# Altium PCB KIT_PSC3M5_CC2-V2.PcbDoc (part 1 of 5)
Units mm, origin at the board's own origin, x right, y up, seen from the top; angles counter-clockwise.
Board outline 131.5 x 87 mm, 6 copper layers (Top Layer, Int1 (GND), Int2 (Sign), Int3 (Sign), Int4 (PWR), Bottom Layer), stack 1.551 mm thick; 371 components, 253 nets, 1359 pads, 837 vias.
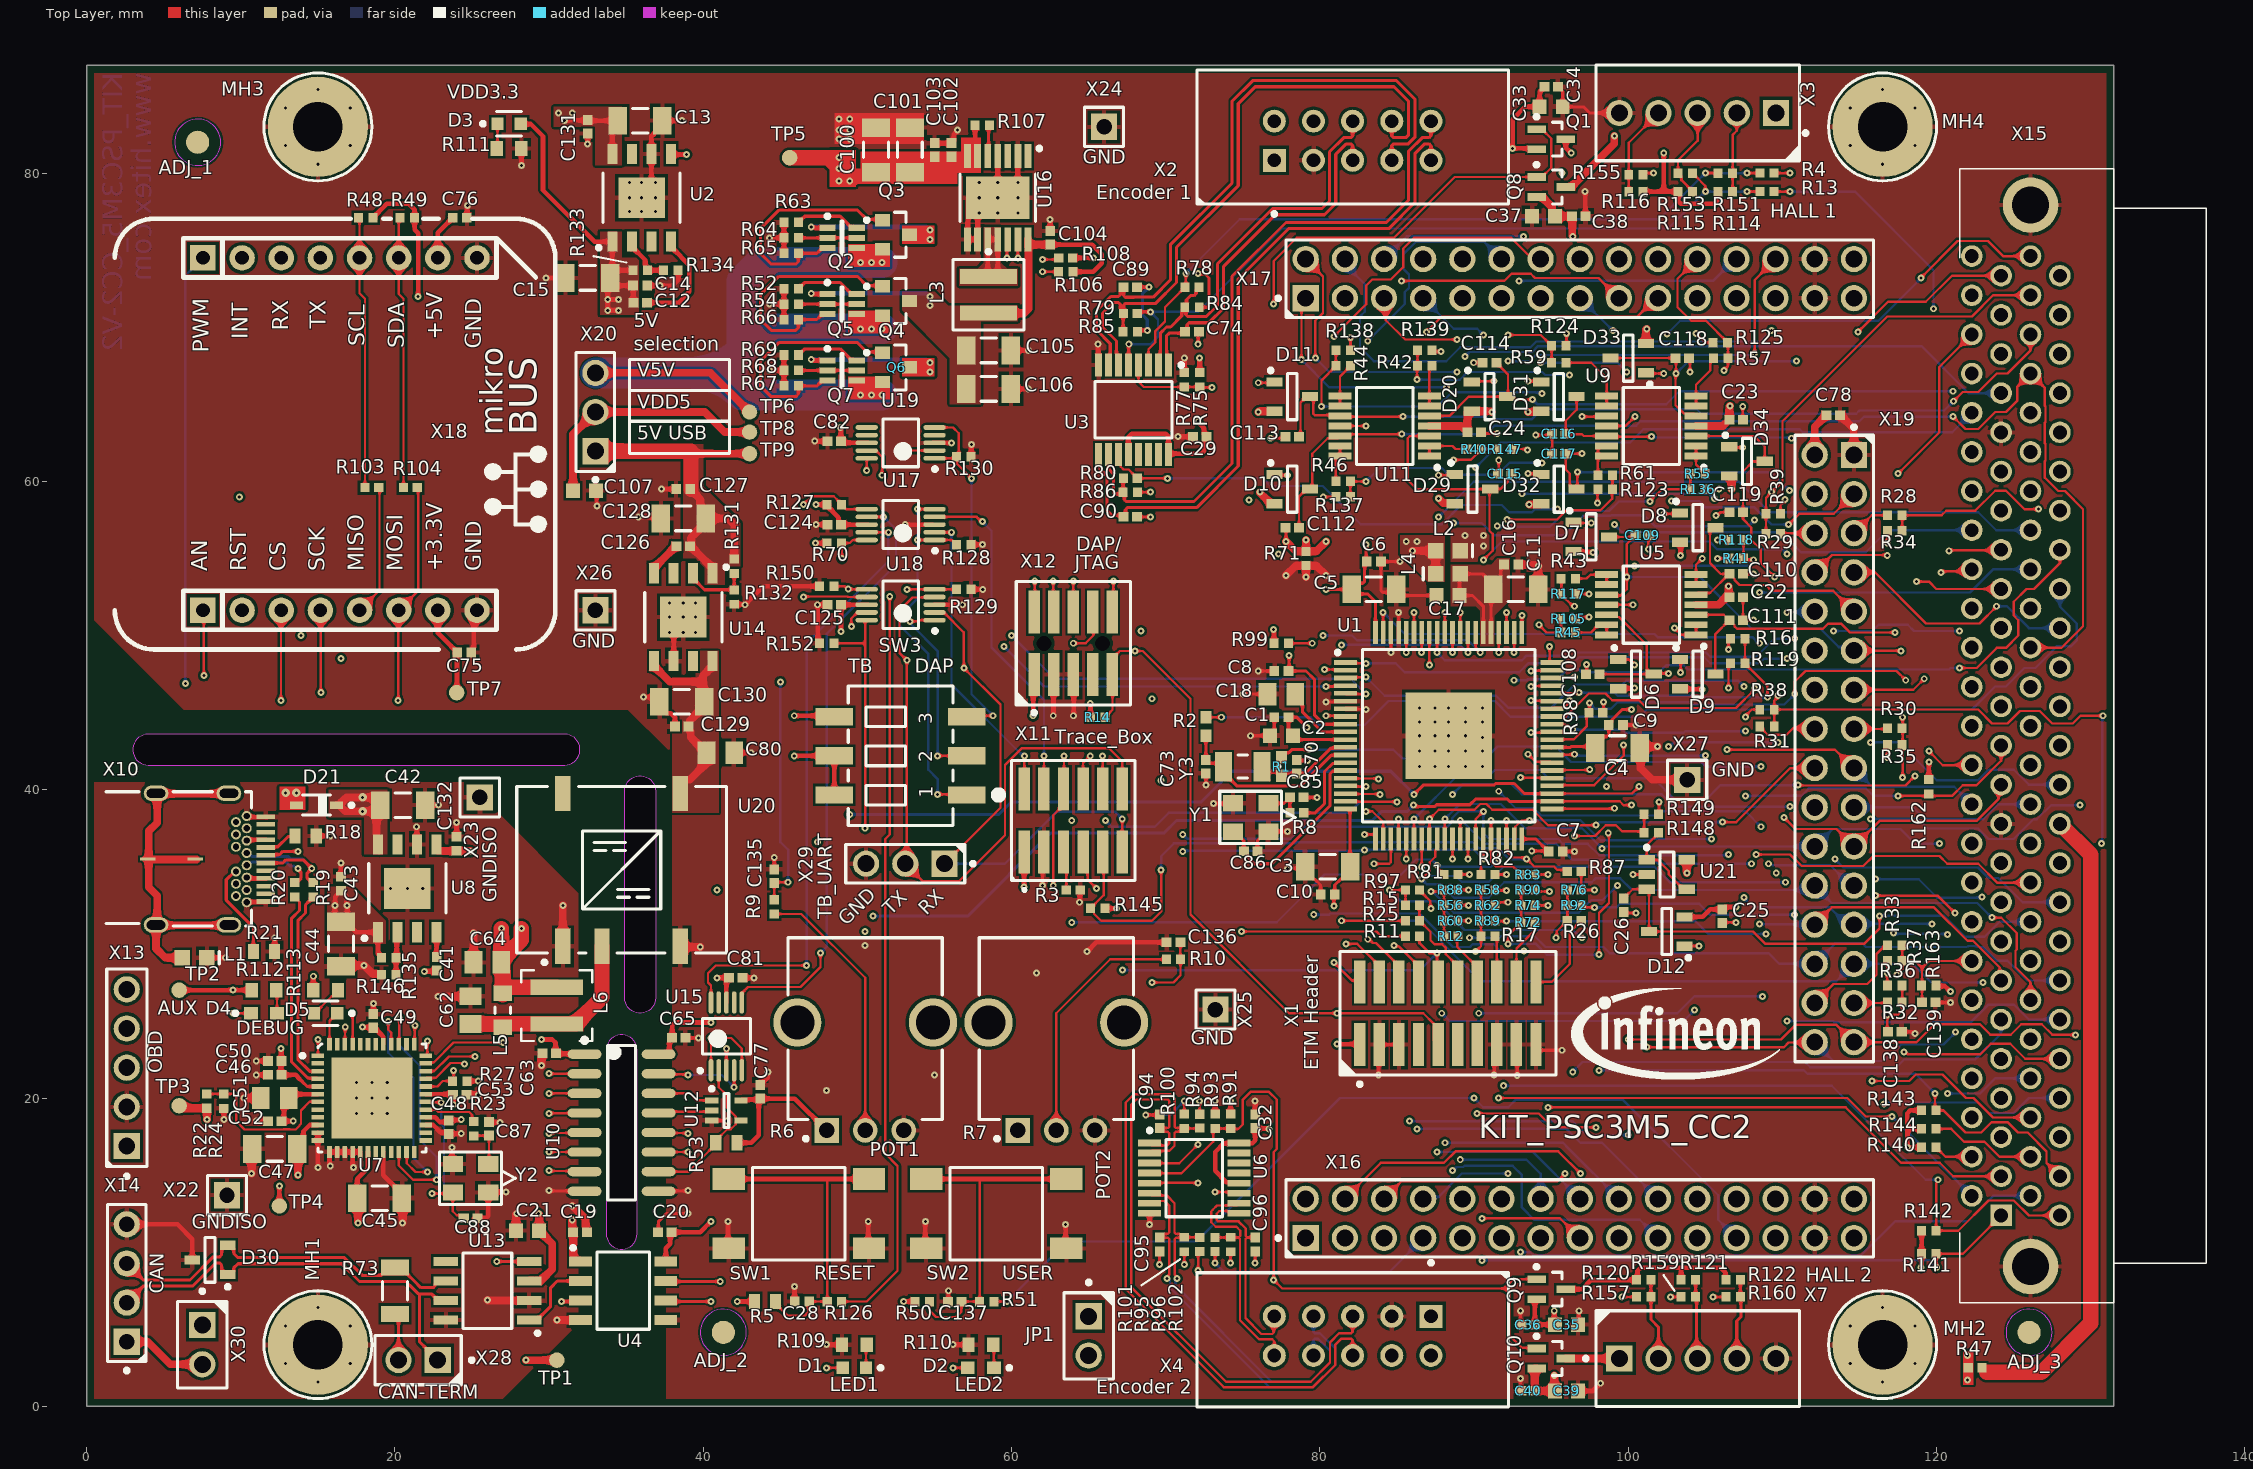
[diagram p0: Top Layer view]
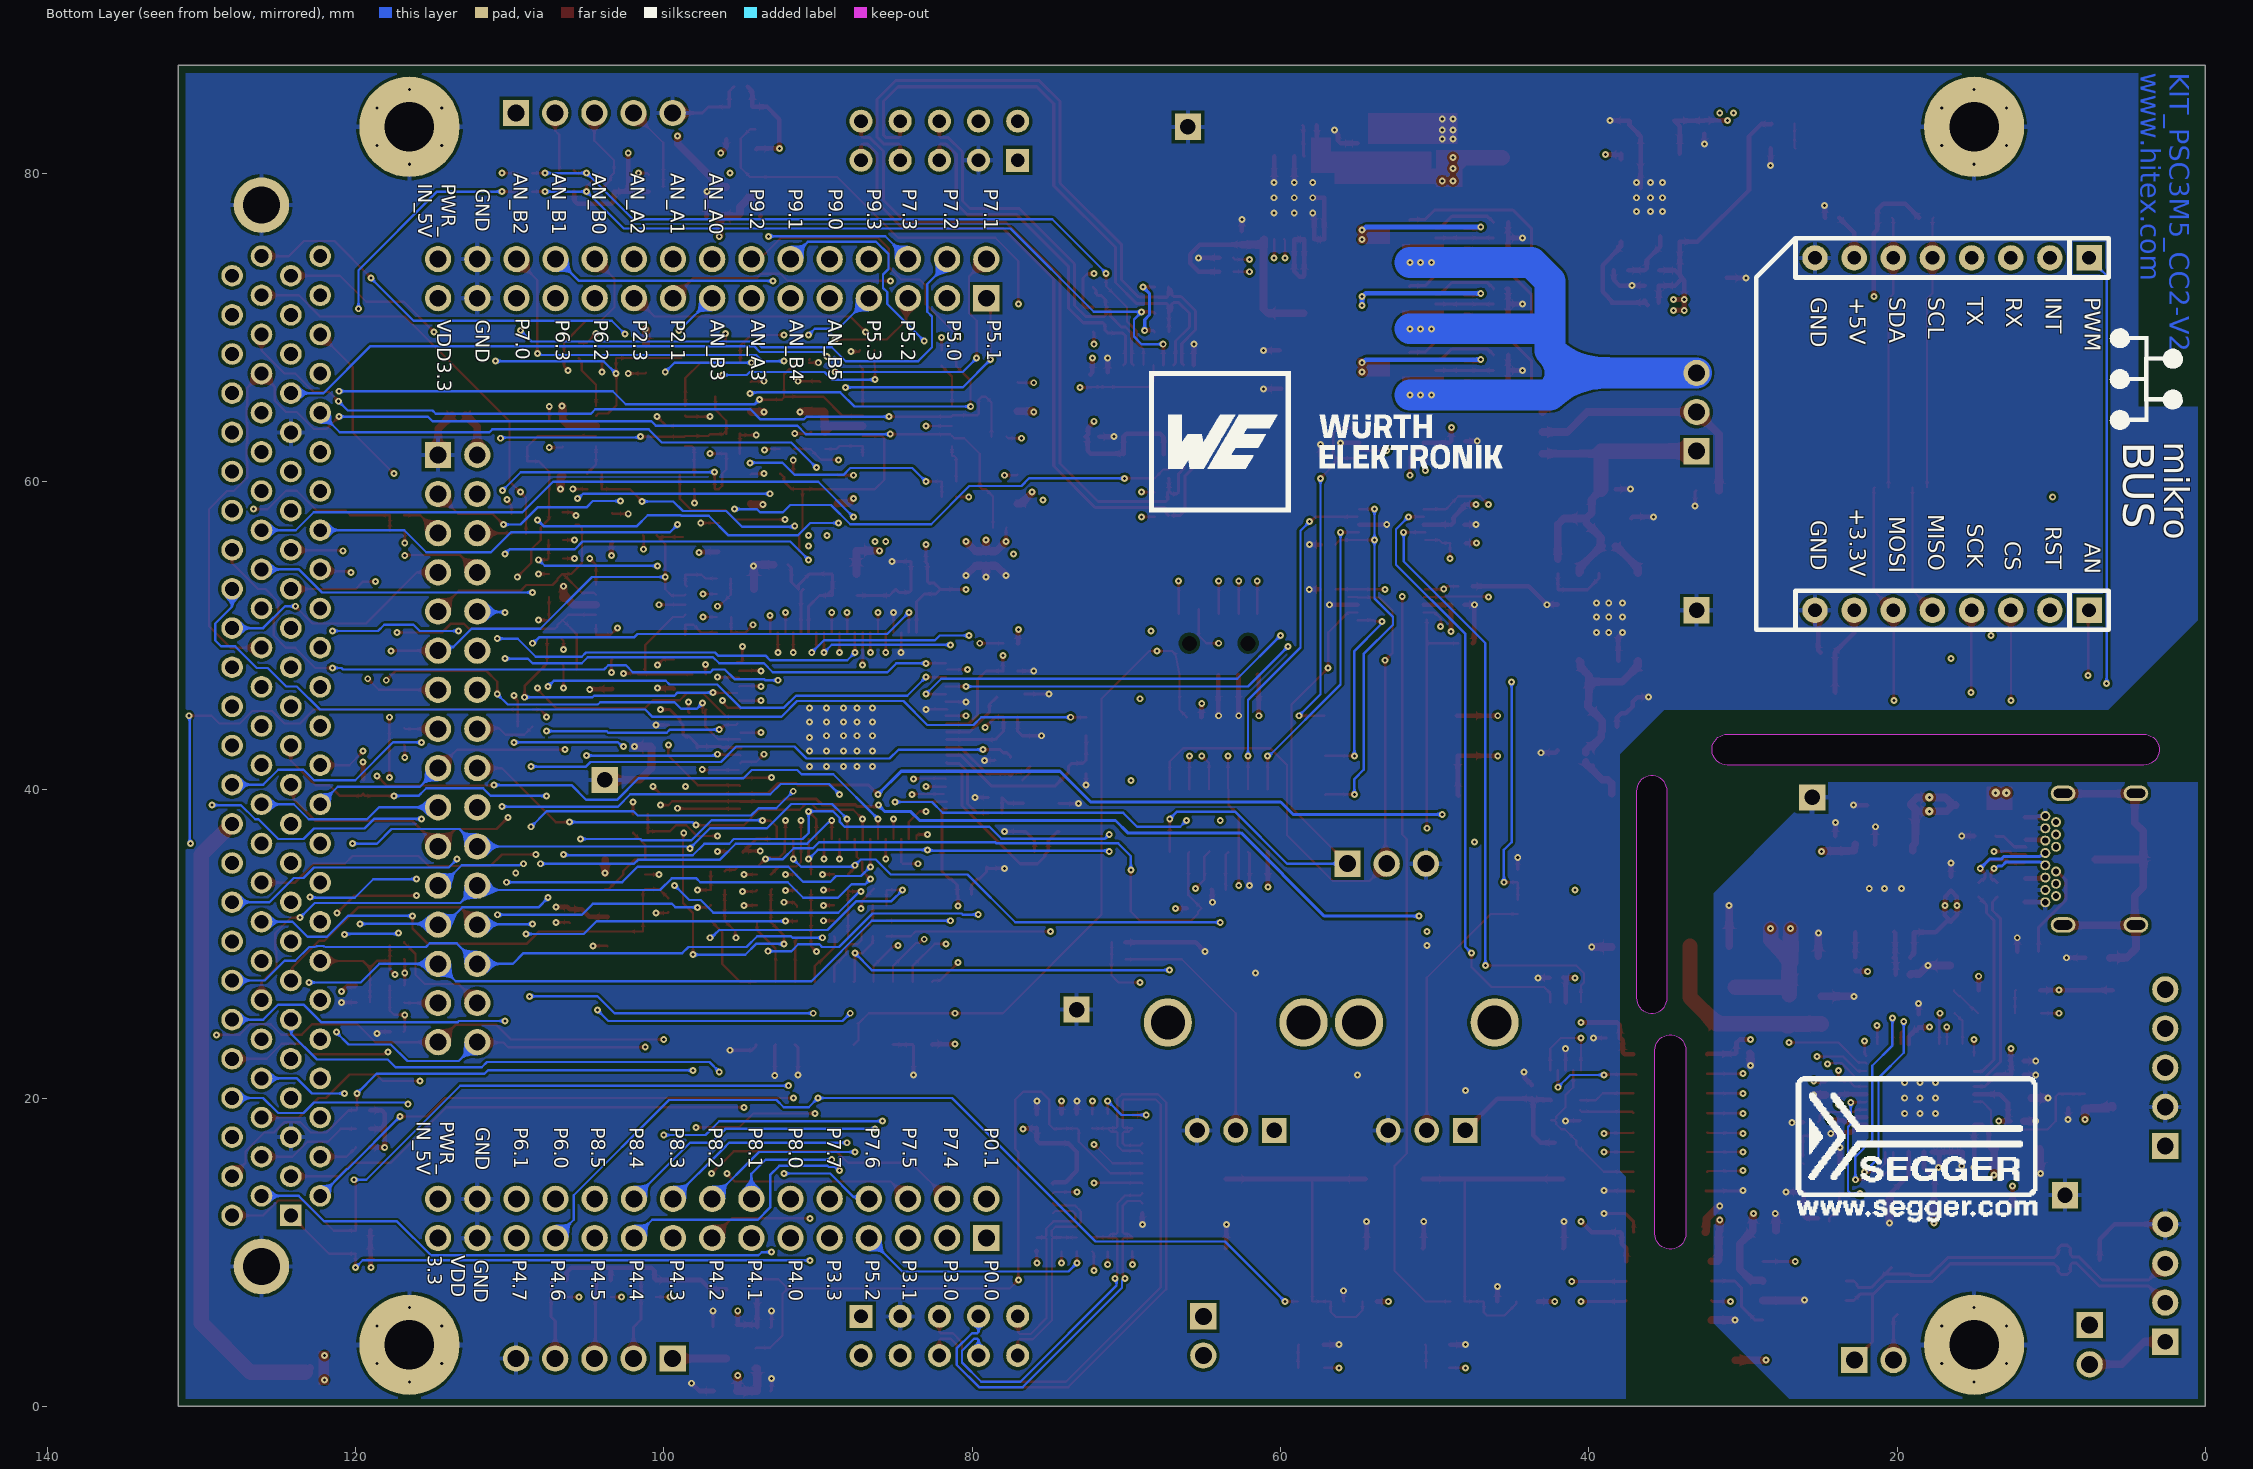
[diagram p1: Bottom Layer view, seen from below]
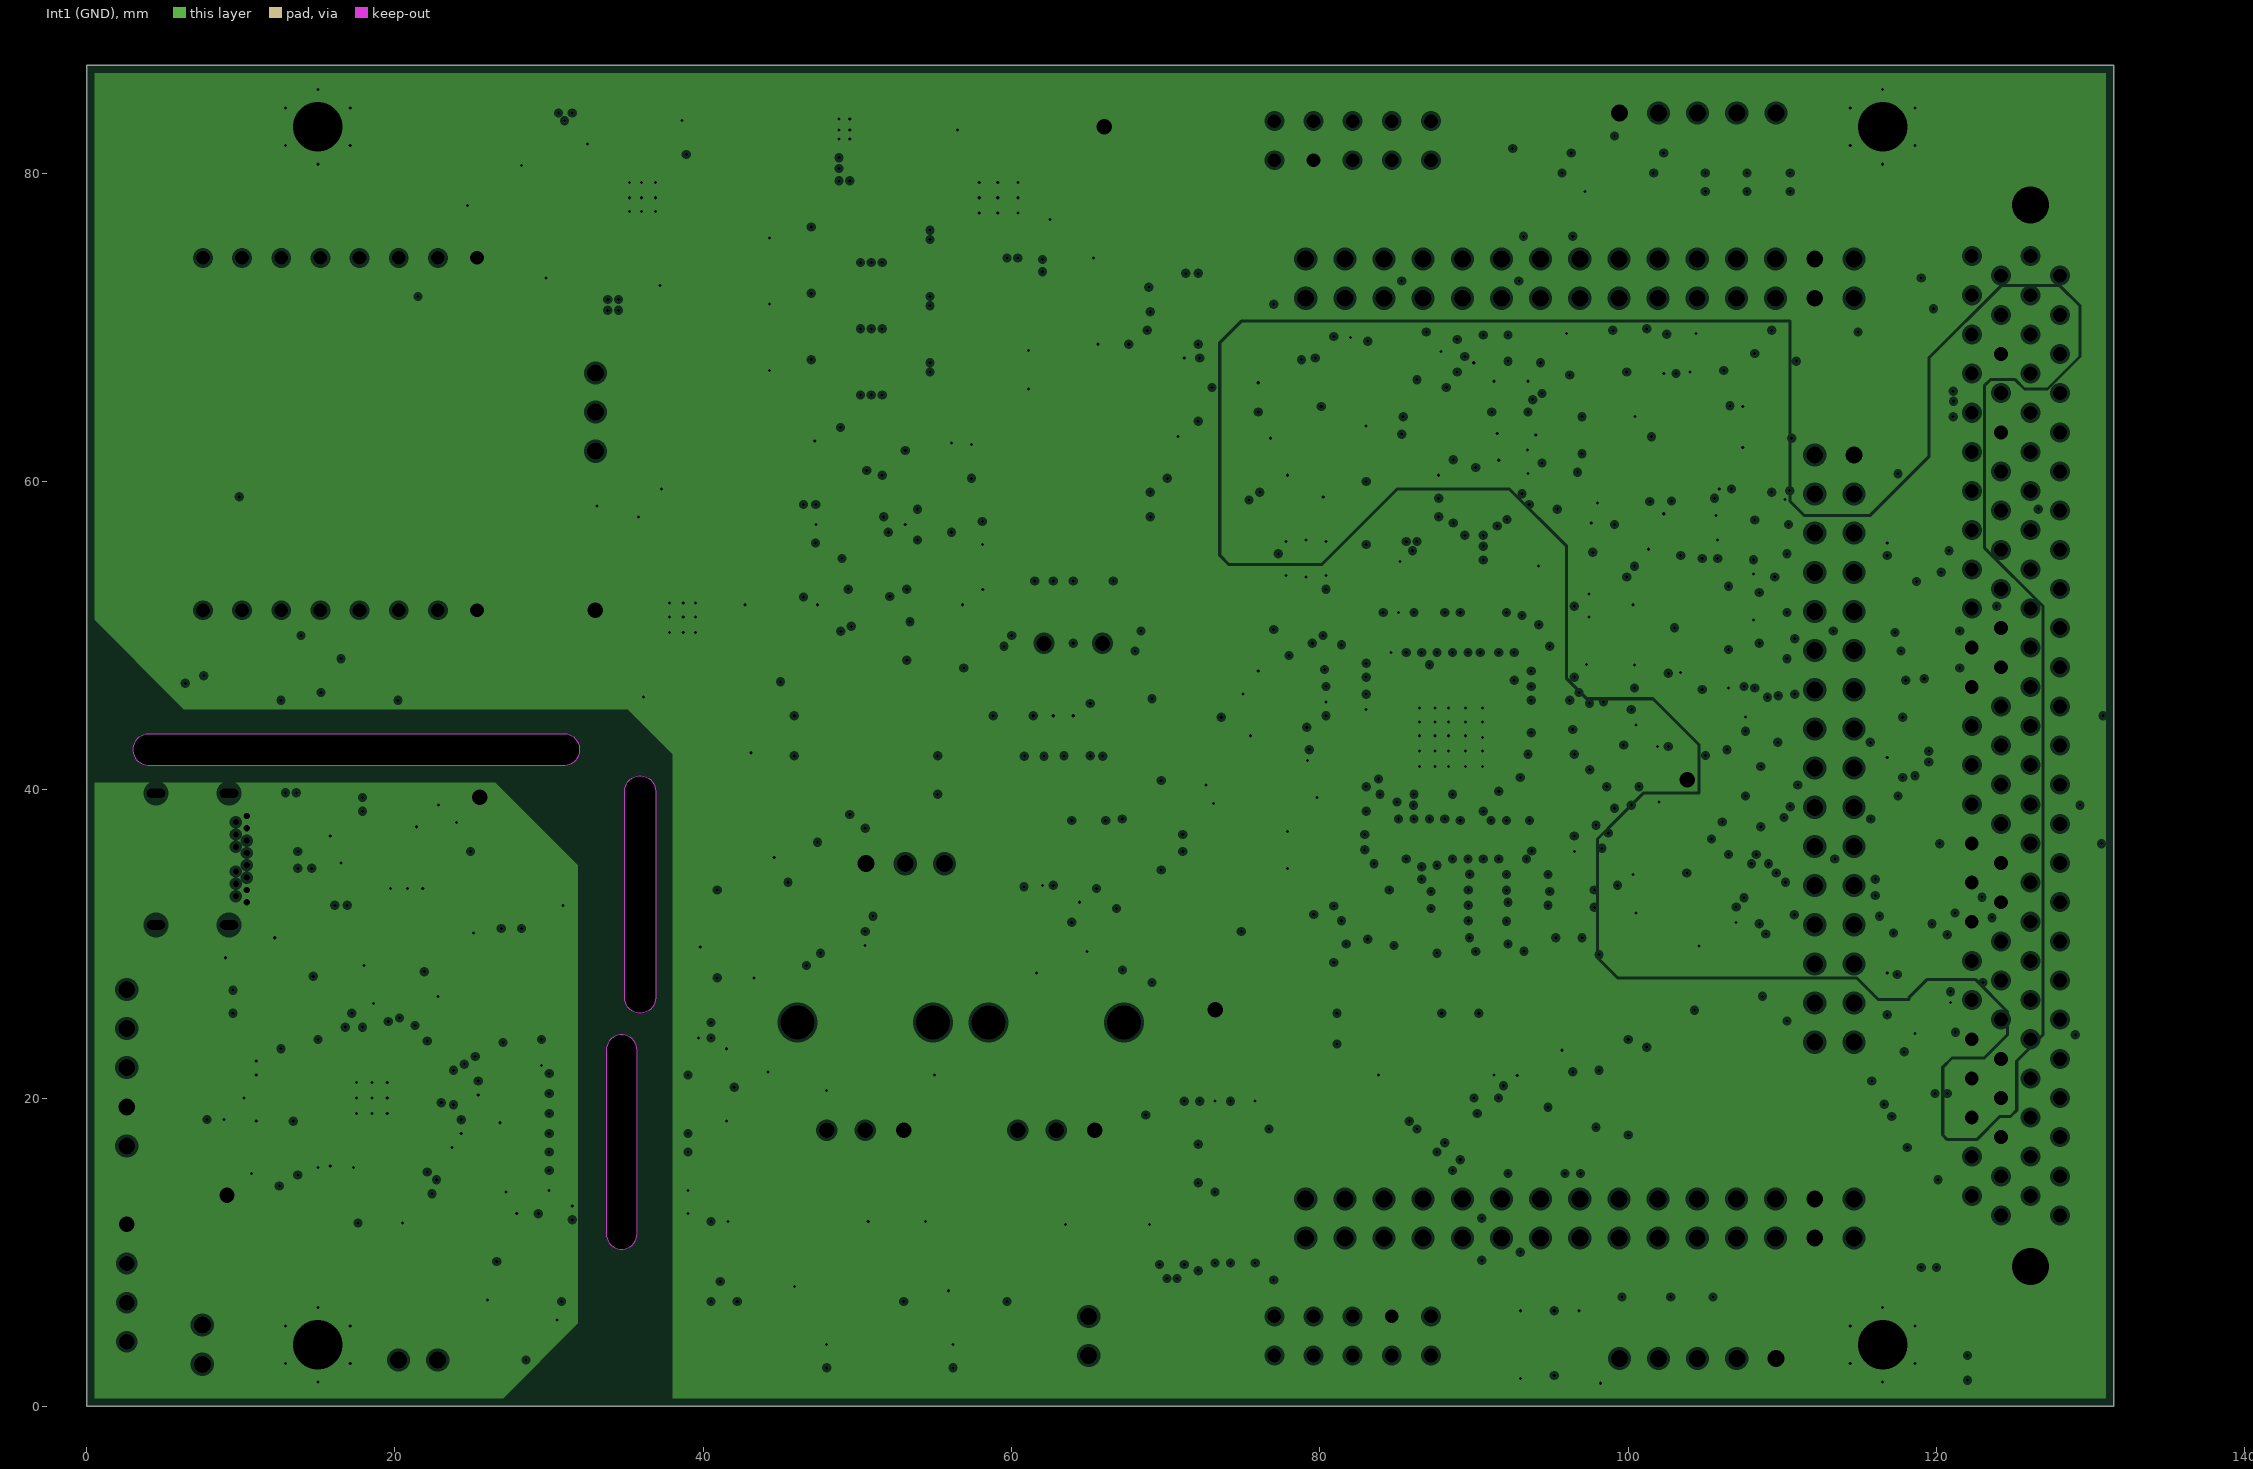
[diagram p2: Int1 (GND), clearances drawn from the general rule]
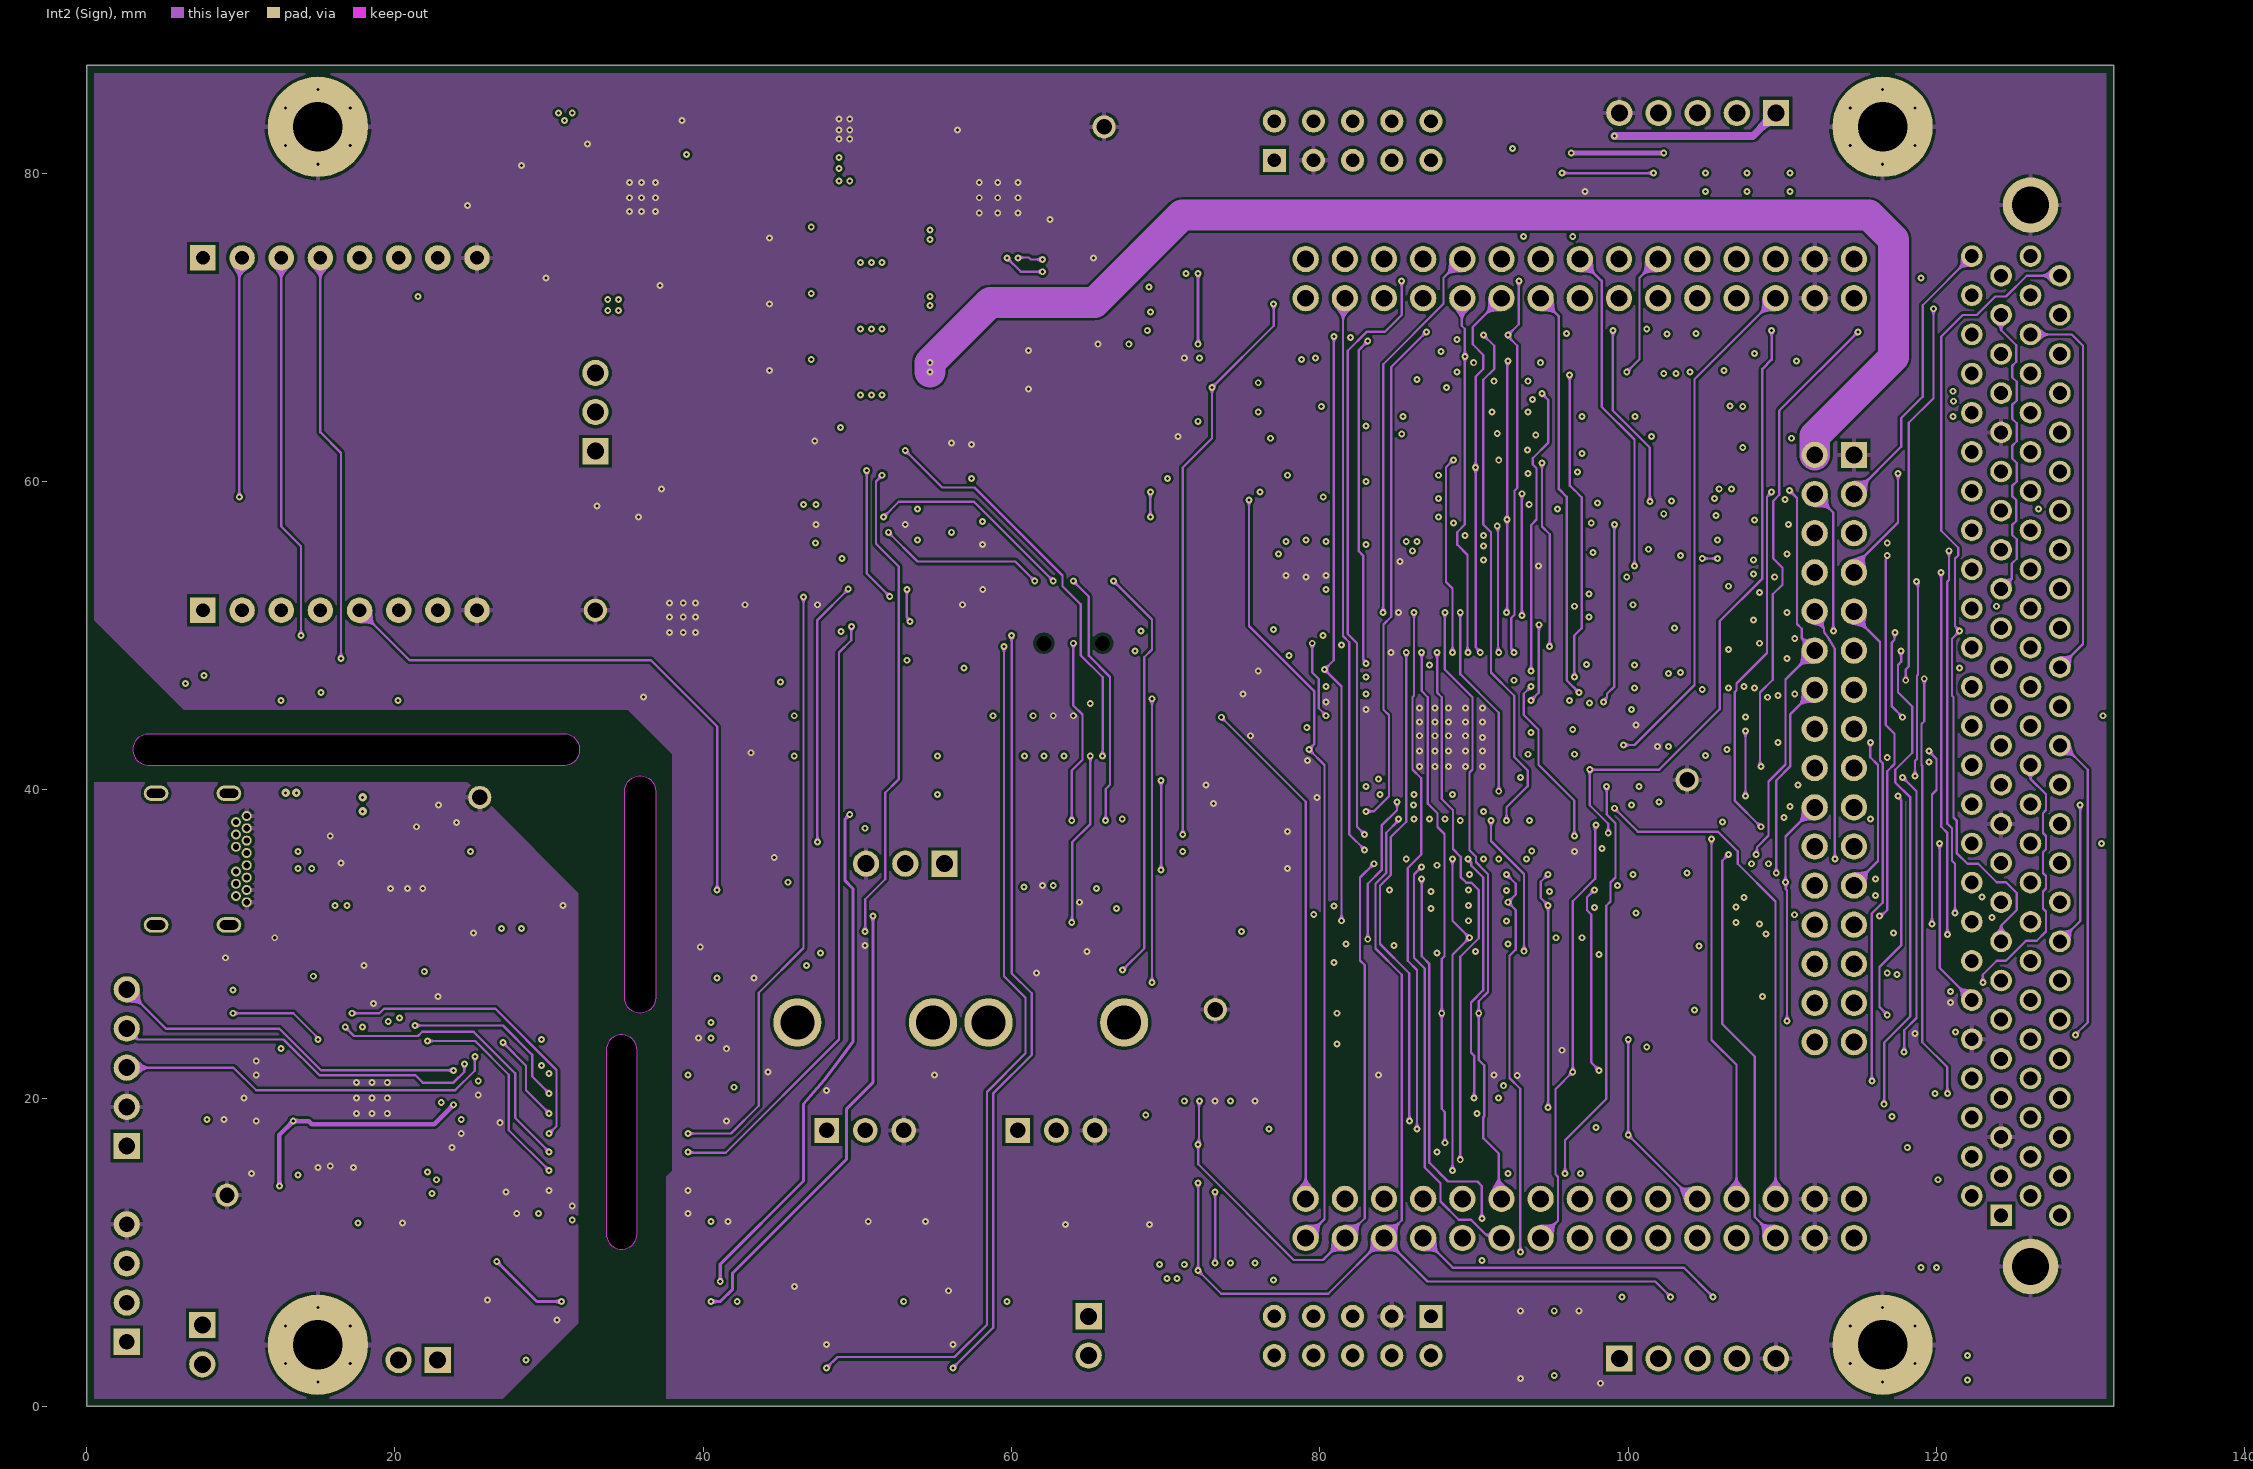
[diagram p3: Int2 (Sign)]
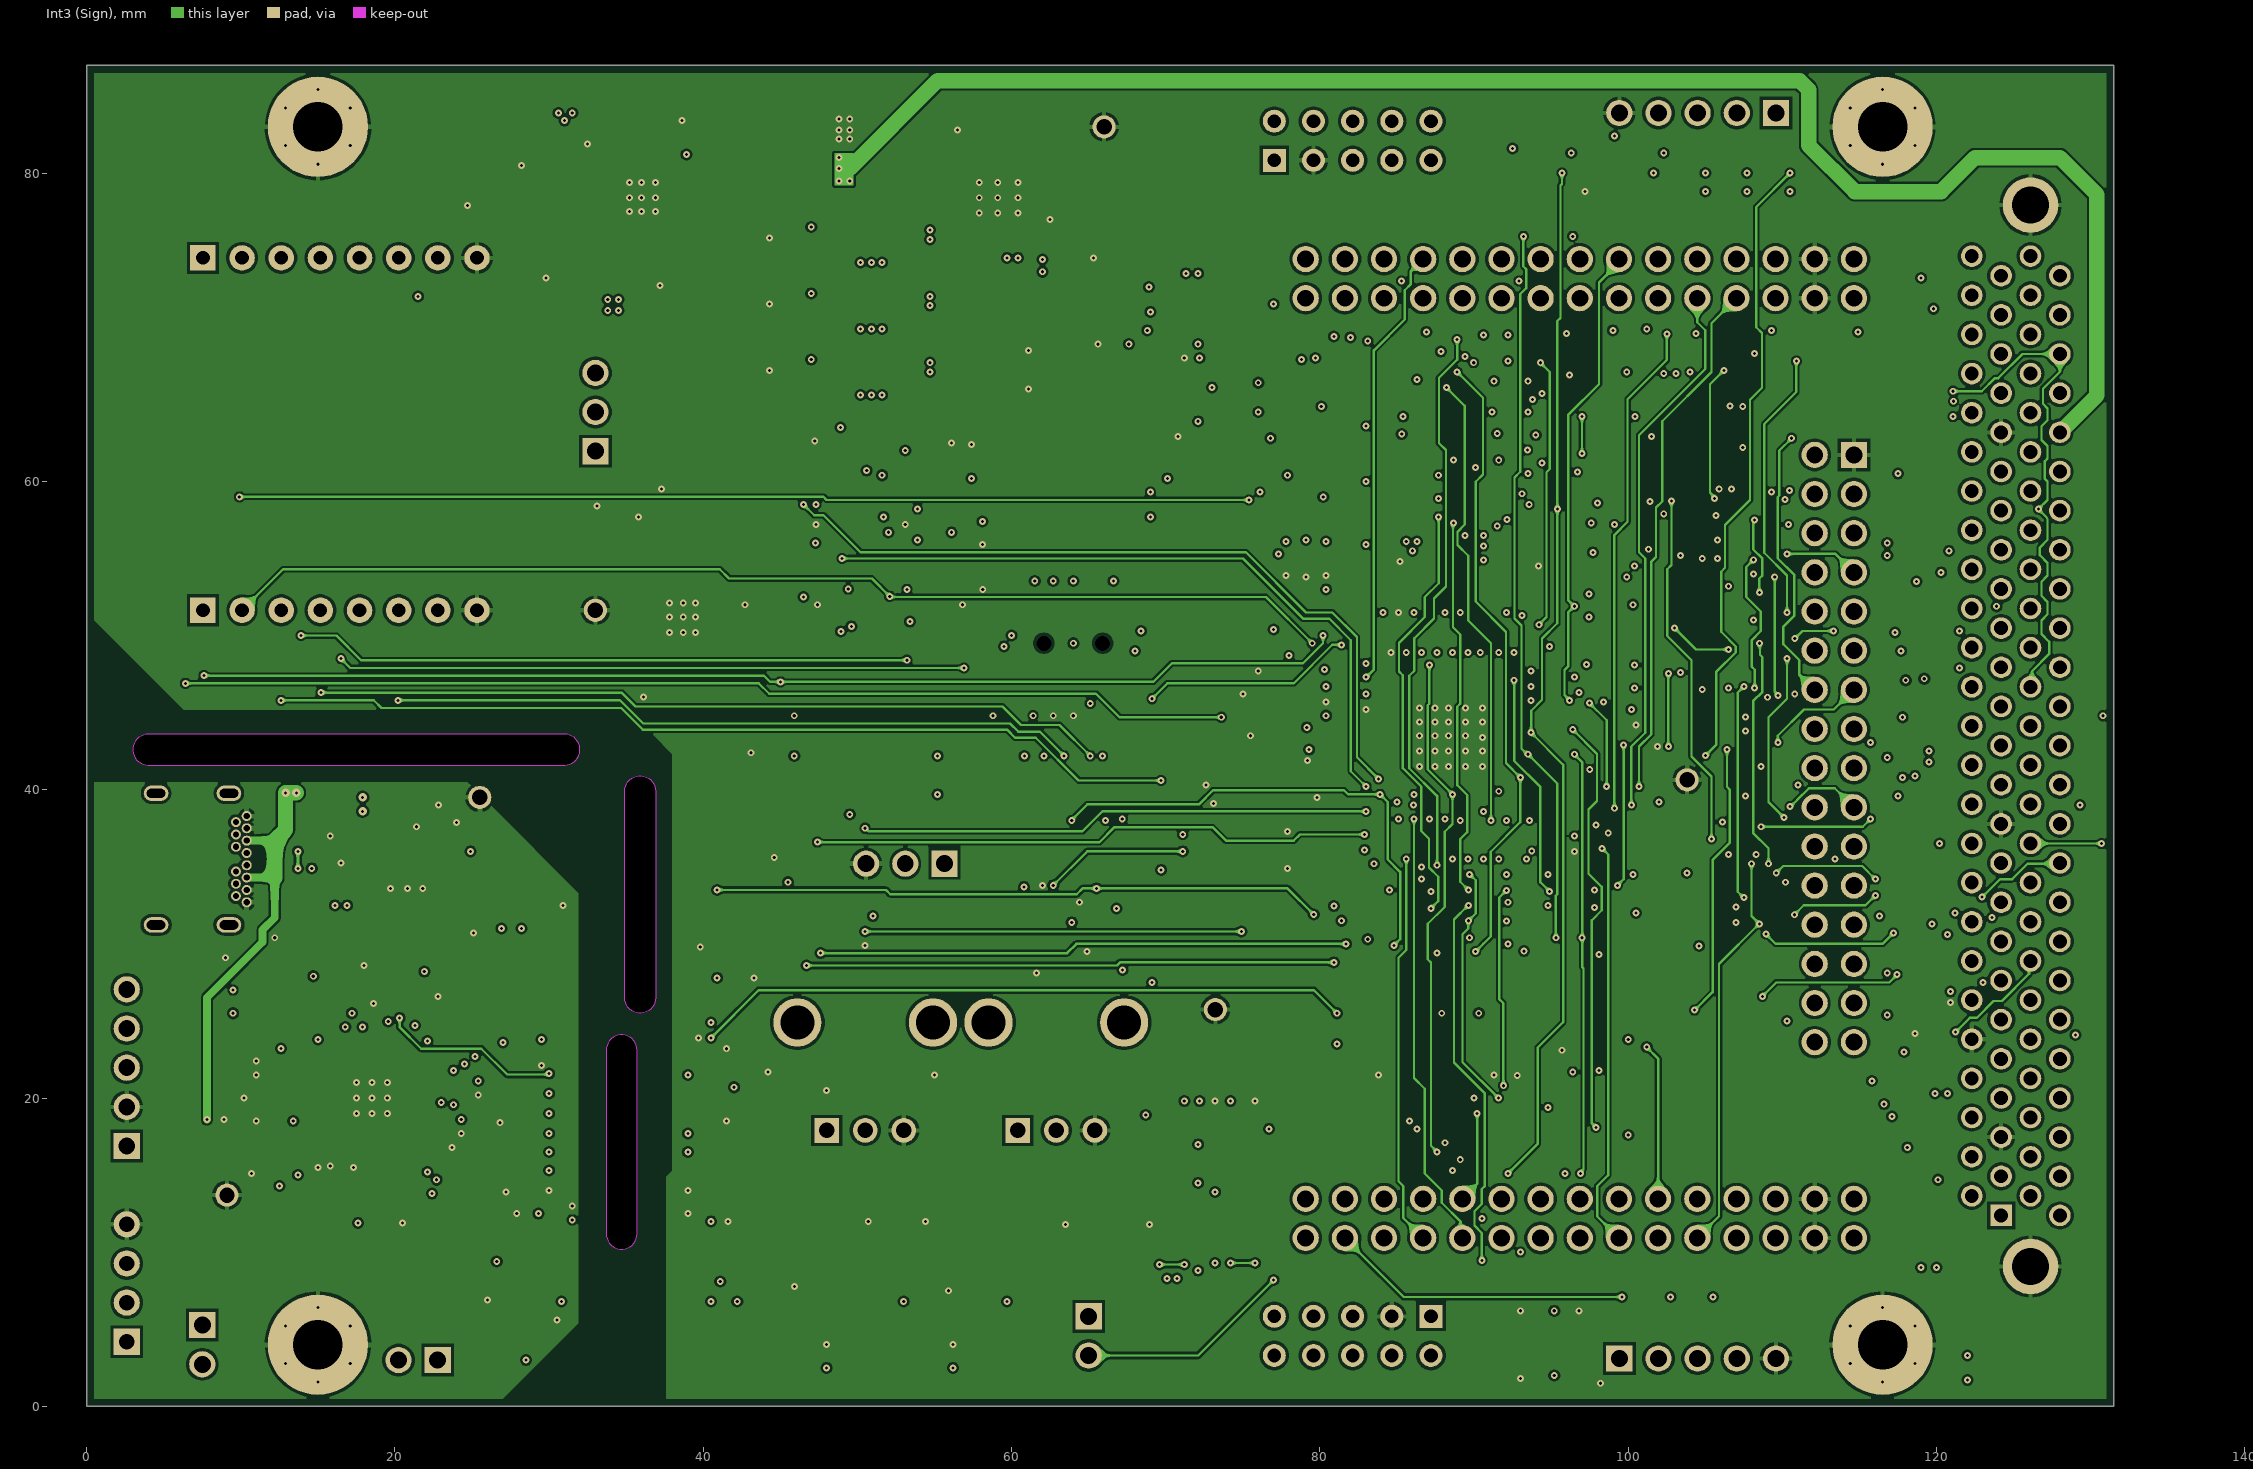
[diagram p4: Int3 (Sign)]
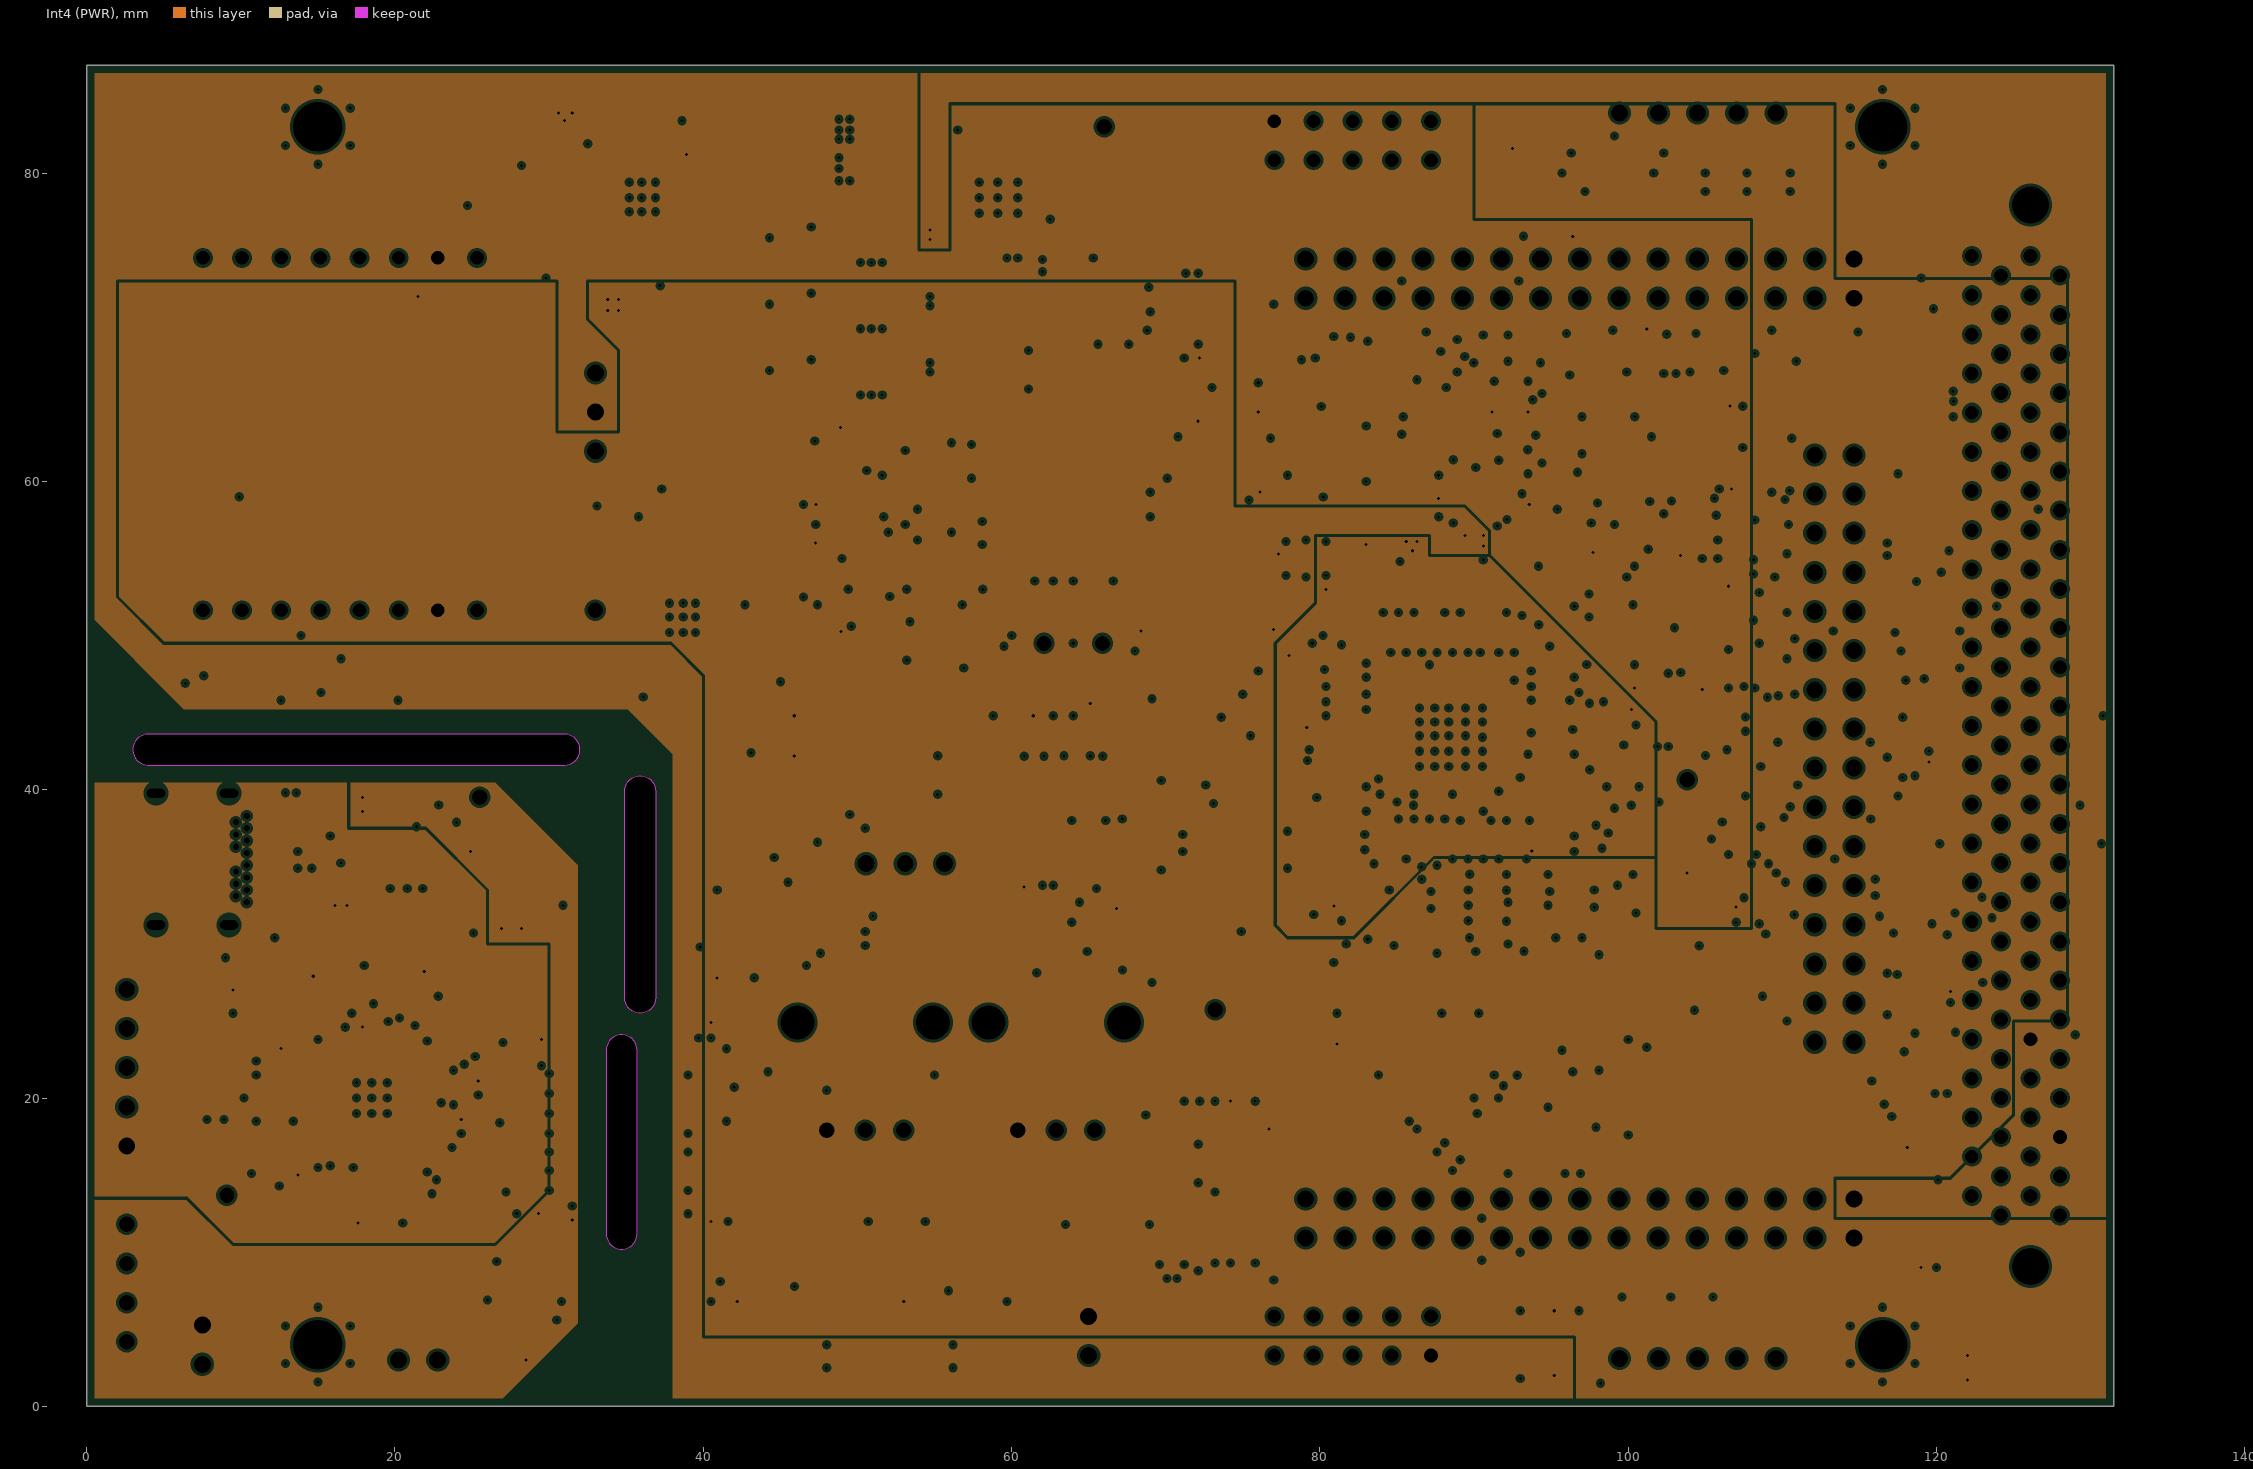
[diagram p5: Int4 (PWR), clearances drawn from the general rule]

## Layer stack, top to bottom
Top Solder: solder mask 0.0254, SM-001, Dk 4
Top Layer: signal copper 0.035
Dielectric 1: prepreg 0.0711, PP-006, Dk 4.1
Dielectric 2: prepreg 0.0711, PP-006, Dk 4.1
Int1 (GND): plane copper 0.035, net (Multiple Nets)
Dielectric 3: core 0.4572, Core-035, Dk 4.7
Int2 (Sign): signal copper 0.035
Dielectric 4: prepreg 0.0711, PP-006, Dk 4.1
Dielectric 5: prepreg 0.0711, PP-006, Dk 4.1
Int3 (Sign): signal copper 0.035
Dielectric 6: core 0.4572, Core-035, Dk 4.7
Int4 (PWR): plane copper 0.035, net (Multiple Nets)
Dielectric 7: prepreg 0.0711, PP-006, Dk 4.1
Dielectric 8: prepreg 0.0711, PP-006, Dk 4.1
Bottom Layer: signal copper 0.035
Bottom Solder: solder mask 0.0254, SM-001, Dk 4

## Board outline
0,0 0,87 131.5,87 131.5,0
cut-out: 33.7,11.2 ccw(c34.7,11.2) 35.7,11.2 35.7,23.1 ccw(c34.7,23.1) 33.7,23.1
cut-out: 34.9,26.5 34.9,39.9 cw(c35.9,39.9) 36.9,39.9 36.9,26.5 cw(c35.9,26.5)
cut-out: 4,41.6 31,41.6 ccw(c31,42.6) 31,43.6 4,43.6 ccw(c4,42.6)

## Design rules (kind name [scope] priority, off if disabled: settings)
BoardOutlineClearance [All] p1: gap=0.254 ignorepadtopadclearanceinfootprint=FALSE except(0: Arc-SplitContinuation Track-SplitContinuation SMDPad-SplitContinuation THPad-SplitContinuation Via-SplitContinuation Fill-SplitContinuation Poly-SplitContinuation Region-SplitContinuation Text-SplitContinuation; 0.5: Poly-OutlineEdge)
Clearance "Clearance Track-Vias" [IsTrack vs IsVia] p1: gap=0.15 ignorepadtopadclearanceinfootprint=FALSE
Clearance "Clearance Vias" [IsVia vs IsVia] p2: gap=0.1 ignorepadtopadclearanceinfootprint=FALSE
Clearance "Clearance All-All" [All] p3: gap=0.15 ignorepadtopadclearanceinfootprint=FALSE except(0.2: Arc-THPad Track-THPad SMDPad-THPad THPad-THPad THPad-Via THPad-Fill THPad-Poly THPad-Region)
DiffPairsRouting [All] p1: maxlimit=0.2 minlimit=0.2 mostfreqgap=0.2 toplayer_minwidth=0.15 toplayer_maxwidth=0.381 toplayer_prefwidth=0.2 midlayer1_minwidth=0.15 midlayer1_maxwidth=0.381 midlayer1_prefwidth=0.2 midlayer2_minwidth=0.15 midlayer2_maxwidth=0.381 midlayer2_prefwidth=0.2 bottomlayer_minwidth=0.15 bottomlayer_maxwidth=0.381 bottomlayer_prefwidth=0.2 maxuncoupledlength=12.7
FabricationTestPointUsage TestPointUsage [All] p1: valid=0 allowmultiple=FALSE
FabricationTestpoint Testpoint [All] p1: side=3 testpointundercomponent=TRUE minsize=1.016 maxsize=2.54 preferedsize=1.524 minholesize=0 maxholesize=1.016 preferedholesize=0.813 testpointgrid=0.025 allowsidetop=TRUE allowsidebottom=TRUE usegrid=TRUE gridtolerance=0
HoleSize [All] p1: absolutevalues=TRUE maxlimit=3.2 minlimit=0.2 maxpercent=80.000 minpercent=20.000
PlaneClearance [All] p1: clearance=0.2
PlaneConnect [All] p1: planeconnectstyle=Direct reliefexpansion=0.508 reliefentries=4 reliefconductorwidth=0.254 reliefairgap=0.254
PolygonConnect "PolygonConnect Pad Direct" [IsPad vs InNet('VDDIO') or InNet('VDDA') or InNet('VDD3.3') or InNet('NetL3_1') or InNet('VDCDC5') or InNet('VDCDC7') or InNet('VSW5V') or InNet('VDD5') or InNet('VISO5') or InNet('VISO3V3')] p1: connectstyle=Direct reliefconductorwidth=0.254 reliefentries=4 polygonreliefangle="90 Angle" airgapwidth=0.254
PolygonConnect "PolygonConnect Via" [All vs IsVia] p2: connectstyle=Direct reliefconductorwidth=0.254 reliefentries=4 polygonreliefangle="90 Angle" airgapwidth=0.254
PolygonConnect "PolygonConnect Pad" [All vs IsPad] p3: connectstyle=Relief reliefconductorwidth=0.3 reliefentries=4 polygonreliefangle="90 Angle" airgapwidth=0.2
RoutingVias [All] p1: holewidth=0.3 width=0.5 viastyle="Through Hole" minholewidth=0.2 minwidth=0.45 maxholewidth=0.2 maxwidth=0.8
SilkToSilkClearance [All] p1: silktosilkclearance=0.1
SilkToSolderMaskClearance SilkscreenOverComponentPads [IsPad] p1: minsilkscreentomaskgap=0.1 clearancetoexposedcopper=TRUE
SolderMaskExpansion [All] p1: expansion=0.02 istentingtop=FALSE
Width [All] p1: maxlimit=2 minlimit=0.15 preferedwidth=0.15
22 further rules are at their usual default settings.

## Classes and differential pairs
differential pair class DIFF120R: CAN ENC1_A ENC1_B ENC1_Z ENC2_A ENC2_B ENC2_Z
component class "Debug Select": C82 C124 C125 R3 R11 R12 R14 R15 R17 R25 R26 R56 R58 R60 R62 R70 R72 R74 R76 R81 R82 R83 R87 R88 R89 R90 R92 R97 R98 R127 R128 R129 R130 SW3 U17 U18 U19 X1 X11 X12 X29
net class Power: AGND GND GNDISO NetL3_1 PWR_IN_5V PWR_IN_24V PWR_OUT_SYS USBSHLD V5V VBUS_C VDCDC5 VDD3.3 VDD5 VDDC VISO3V3 VISO5 VPWR5V VSW5V
component class "Analog Signal Converter": C22 C23 C24 C25 C26 C108 C109 C110 C111 C112 C113 C114 C115 C116 C117 C118 C119 D6 D7 D8 D9 D10 D11 D12 D20 D29 D31 D32 D33 D34 R16 R40 R41 R42 R43 R44 R45 R46 R55 R57 R59 R61 R71 R105 R117 R118 R119 R123 R124 R125 R136 R137 R138 R139 R147 R148 R149 U5 U9 U11 U21
differential pair class DIFF90R: USB_D USB_DS
component class "OBD Debugger": C41 C42 C43 C44 C45 C46 C47 C48 C49 C50 C51 C52 C53 C87 C88 C132 D4 D5 D21 L1 R18 R19 R20 R21 R22 R23 R24 R27 R112 R113 R135 R146 TP1 TP2 TP3 TP4 U7 U8 X10 X13 Y2
component class "Isolation and Power": C19 C20 C21 C62 C63 C64 C65 C77 C80 C81 C100 C101 C102 C103 C104 C105 C106 C107 C126 C127 C128 C129 C130 D30 L3 L5 L6 Q2 Q3 Q4 Q5 Q6 Q7 R52 R53 R54 R63 R64 R65 R66 R67 R68 R69 R73 R106 R107 R108 R131 R132 TP5 TP6 TP7 TP8 TP9 U4 U10 U12 U13 U14 U15 U16 U20 X14 X20 X28 X30
component class PSoC-C3: C1 C2 C3 C4 C5 C6 C7 C8 C9 C10 C11 C12 C13 C14 C15 C16 C17 C18 C28 C70 C73 C85 C86 C131 C135 C136 C137 D1 D2 D3 L2 L4 R1 R2 R5 R6 R7 R8 R9 R10 R50 R51 R109 R110 R111 R126 R133 R134 R150 R152 SW1 SW2 U1 U2 Y1 Y3
component class "Expansion Headers": ADJ_1 ADJ_2 ADJ_3 C75 C76 C78 C138 C139 MH1 MH2 MH3 MH4 R28 R29 R30 R31 R32 R33 R34 R35 R36 R37 R38 R39 R47 R48 R49 R99 R103 R104 R140 R141 R142 R143 R144 R145 R162 R163 X15 X16 X17 X18 X19 X22 X23 X24 X25 X26 X27
component class "Encoder and Hall Sensor": C29 C32 C33 C34 C35 C36 C37 C38 C39 C40 C74 C89 C90 C94 C95 C96 JP1 Q1 Q8 Q9 Q10 R4 R13 R75 R77 R78 R79 R80 R84 R85 R86 R91 R93 R94 R95 R96 R100 R101 R102 R114 R115 R116 R120 R121 R122 R151 R153 R155 R157 R159 R160 U3 U6 X2 X3 X4 X7
differential pair ENC2_Z: +ENC2_Z_P -ENC2_Z_N
differential pair ENC2_B: +ENC2_B_P -ENC2_B_N
differential pair ENC2_A: +ENC2_A_P -ENC2_A_N
differential pair ENC1_Z: +ENC1_Z_P -ENC1_Z_N
differential pair ENC1_B: +ENC1_B_P -ENC1_B_N
differential pair ENC1_A: +ENC1_A_P -ENC1_A_N
differential pair CAN: +CAN_P -CAN_N
differential pair USB_D: +USB_D_P -USB_D_N
differential pair USB_DS: +USB_DS_P -USB_DS_N

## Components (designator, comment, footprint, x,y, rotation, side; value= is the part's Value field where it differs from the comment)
ADJ_1 "Fiducial Round 1.5mm" FIDUCIAL_ROUND_1.5MM 7.2,82 r90 top
ADJ_2 "Fiducial Round 1.5mm" FIDUCIAL_ROUND_1.5MM 41.3,4.8 r90 top
ADJ_3 "Fiducial Round 1.5mm" FIDUCIAL_ROUND_1.5MM 126,4.8 r90 top
C1 "100nF" CAPC1005X60N 77.5,44.7 r0 top
C2 "1uF" CAPC1608X90N-1 77.5,43.5 r0 top
C3 "10uF" CAPC3216X180N 80.5,35 r0 top
C4 "10uF" CAPC3216X180N 99.3,42.7 r180 top
C5 "10uF" CAPC3216X180N 83.5,53 r180 top
C6 "100nF" CAPC1005X60N 83.5,54.8 r180 top
C7 "100nF" CAPC1005X60N 95.3,36 r180 top
C8 "100nF" CAPC1005X60N 77.5,47.7 r0 top
C9 "100nF" CAPC1005X60N 99.2,44.2 r180 top
C10 "100nF" CAPC1005X60N 80.5,33.2 r0 top
C11 "10uF" CAPC3216X180N 92.7,53 r180 top
C12 "10nF" CAPC1005X55N-0 35.9,71.6 r180 top
C13 "10uF" CAPC3216X180N 35.9,83.4 r180 top
C14 "100nF" CAPC1005X60N 35.9,72.7 r180 top
C15 "10uF" CAPC3216X180N 32.5,73.2 r0 top
C16 "100nF" CAPC1005X60N 92.4,54.6 r180 top
C17 "1uF" CAPC1608X90N-1 88.3,52.6 r0 top
C18 "4.7uF" CAPC2013X145N-3 77.5,46.2 r0 top
C19 "100nF" CAPC1005X55N-0 32,11.3 r0 top
C20 "100nF" CAPC1005X55N-0 37.5,11.3 r180 top
C21 "1uF" CAPC1608X90N-1 28.6,11.4 r0 top
C22 "100nF" CAPC1005X55N-0 107,52.5 r180 top
C23 "100nF" CAPC1005X55N-0 107,64 r180 top
C24 "100nF" CAPC1005X55N-0 90,63.2 r180 top
C25 "100nF" CAPC1005X55N-0 106.1,31.8 r90 top
C26 "1nF" CAPC1005X55N-0 99.7,32.5 r90 top
C28 "100nF" CAPC1005X60N 46.4,6.8 r0 top
C29 "100nF" CAPC1005X55N-0 72.2,62.9 r180 top
C32 "100nF" CAPC1005X55N-0 75.8,18.5 r90 top
C33 "1uF" CAPC1608X90N-1 95,84.3 r180 top
C34 "100nF" CAPC1005X55N-0 95,85.6 r180 top
C35 "1uF" CAPC1608X90N-1 96,5.3 r180 top
C36 "100nF" CAPC1005X55N-0 93.5,5.3 r0 top
C37 "1uF" CAPC1608X90N-1 94.5,77.2 r0 top
C38 "100nF" CAPC1005X55N-0 96.8,77.2 r180 top
C39 "1uF" CAPC1608X90N-1 96,1 r180 top
C40 "100nF" CAPC1005X55N-0 93.5,1 r0 top
C41 "10nF" CAPC1005X55N-0 22.7,28.7 r270 top
C42 "10uF" CAPC3216X180N 20.5,39 r180 top
C43 "100nF" CAPC1005X60N 16.5,33.9 r270 top
C44 "10uF" CAPC3216X180N 16.5,30 r90 top
C45 "10uF" CAPC3216X180N 19,13.5 r180 top
C46 "100nF" CAPC1005X55N-0 12.2,21.502 r0 top
C47 "10uF" CAPC3216X180N 12.2,16.702 r0 top
C48 "100nF" CAPC1005X55N-0 23.5,18.1 r90 top
C49 "100nF" CAPC1005X55N-0 18.6,25 r270 top
C50 "100nF" CAPC1005X55N-0 12.2,22.402 r0 top
C51 "4.7uF" CAPC2013X145N-3 12.2,20.002 r0 top
C52 "100nF" CAPC1005X55N-0 12.2,18.502 r0 top
C53 "100nF" CAPC1005X55N-0 24.2,20.2 r180 top
C62 "4.7uF" CAPC2013X145N-3 24.9,25.7 r270 top
C63 "100nF" CAPC1005X55N-0 30,22.9 r0 top
C64 "4.7uF" CAPC2013X145N-3 26,28.8 r0 top
C65 "100nF" CAPC1005X55N-0 38.4,23.9 r180 top
C70 "15pF" CAPC1005X55N-0 78.5,41.5 r270 top
C73 "15pF" CAPC1005X55N-0 72.6,41.5 r90 top
C74 "15nF" CAPC1005X55N-0 71.7,69.7 r180 top
C75 "100nF" CAPC1005X60N 24.5,48.9 r180 top
C76 "100nF" CAPC1005X60N 24.2,77.1 r180 top
C77 "100nF" CAPC1005X55N-0 43.7,20.4 r270 top
C78 "100nF" CAPC1005X55N-0 113.3,64.3 r0 top
C80 "4.7uF" CAPC2013X145N-3 41.1,42.4 r180 top
C81 "100nF" CAPC1005X55N-0 42.1,27.8 r180 top
C82 "100nF" CAPC1005X55N-0 48.5,62.6 r0 top
C85 "18pF" CAPC1005X55N-0 78.5,39.5 r180 top
C86 "18pF" CAPC1005X55N-0 75.5,36 r180 top
C87 "15pF" CAPC1005X55N-0 26.1,18 r270 top
C88 "15pF" CAPC1005X55N-0 24.9,12.202 r180 top
C89 "15nF" CAPC1005X55N-0 67.7,72.6 r180 top
C90 "15nF" CAPC1005X55N-0 67.7,57.7 r180 top
C94 "15nF" CAPC1005X55N-0 69.6,18.5 r270 top
C95 "15nF" CAPC1005X55N-0 69.6,10.5 r90 top
C96 "15nF" CAPC1005X55N-0 75.8,10.5 r90 top
C100 "10uF" CAPC3216X180N 51.2,81.5 r270 top
C101 "10uF" CAPC3216X180N 53.4,81.5 r270 top
C102 "100nF" CAPC1005X55N-0 56.1,81.5 r90 top
C103 "2.2nF" CAPC1005X55N-0 55,81.5 r270 top
C104 "100nF" CAPC1005X55N-0 62.5,75.8 r270 top
C105 "10uF" CAPC3216X180N 58.5,68.5 r180 top
C106 "10uF" CAPC3216X180N 58.5,66 r180 top
C107 "1uF" CAPC1608X90N-1 32.3,59.4 r180 top
C108 "1nF" CAPC1005X55N-0 97.7,47.5 r0 top
C109 "1nF" CAPC1005X55N-0 100.9,56.5 r180 top
C110 "1nF" CAPC1005X55N-0 107,54 r180 top
C111 "22pF" CAPC1005X55N-0 107,51 r180 top
C112 "1nF" CAPC1005X55N-0 78.2,57 r0 top
C113 "1nF" CAPC1005X55N-0 78.2,62.9 r0 top
C114 "1nF" CAPC1005X55N-0 91,67.7 r0 top
C115 "22pF" CAPC1005X55N-0 92,60.5 r0 top
C116 "1nF" CAPC1005X55N-0 95.5,63.1 r0 top
C117 "1nF" CAPC1005X55N-0 95.5,61.8 r0 top
C118 "1nF" CAPC1005X55N-0 103.5,68 r180 top
C119 "22pF" CAPC1005X55N-0 107,58 r0 top
C124 "100nF" CAPC1005X55N-0 48.5,57.2 r0 top
C125 "100nF" CAPC1005X55N-0 48.5,52 r0 top
C126 "10nF" CAPC1005X55N-0 38.7,55.8 r0 top
C127 "100nF" CAPC1005X60N 38.7,59.5 r0 top
C128 "10uF" CAPC3216X180N 38.7,57.6 r0 top
C129 "100nF" CAPC1005X55N-0 38.6,44.1 r0 top
C130 "10uF" CAPC3216X180N 38.6,45.7 r0 top
C131 "100nF" CAPC1005X55N-0 32.5,83 r90 top
C132 "100nF" CAPC1005X60N 24,36.5 r270 top
C135 "15nF" CAPC1005X55N-0 44.6,34.4 r90 top
C136 "15nF" CAPC1005X55N-0 70.5,30.1 r180 top
C137 "15nF" CAPC1005X55N-0 56.3,6.8 r180 top
C138 "15nF" CAPC1005X55N-0 117.3,24.3 r0 top
C139 "15nF" CAPC1005X55N-0 119.5,26.2 r0 top
D1 "Yellow" LEDSC160X80X40-2N 49.8,2.5 r180 top
D2 "Red" LEDSC160X80X80-2N 58,2.5 r180 top
D3 "Green" LEDSC160X80X40-2N 27.4,83.2 r0 top
D4 "Red" LEDSC160X80X80-2N 11.5,25.5 r0 top
D5 "Green" LEDSC160X80X40-2N 15.5,25.5 r180 top
D6 "BAT54S-E3-08" SOT95P248X115-3N 100.5,47.5 r0 top
D7 "BAT54S-E3-08" SOT95P248X115-3N 97.6,56.4 r0 top
D8 "BAT54S-E3-08" SOT95P248X115-3N 104.5,57 r0 top
D9 "BAT54S-E3-08" SOT95P248X115-3N 104.5,47.5 r0 top
D10 "BAT54S-E3-08" SOT95P248X115-3N 78.2,59.5 r0 top
D11 "BAT54S-E3-08" SOT95P248X115-3N 78.2,65.5 r0 top
D12 "BAT54S-E3-08" SOT95P248X115-3N 102.5,30.8 r180 top
D20 "BAT54S-E3-08" SOT95P248X115-3N 91,65.5 r0 top
D21 "BAS3010A-03W" SOD2513X110N 14.9,39 r180 top
D29 "BAT54S-E3-08" SOT95P248X115-3N 89.9,59.5 r0 top
D30 "PESD2CAN,215" SOT95P230X110-3N 8,9.5 r180 top
D31 "BAT54S-E3-08" SOT95P248X115-3N 95.5,65.5 r0 top
D32 "BAT54S-E3-08" SOT95P248X115-3N 95.5,59.5 r0 top
D33 "BAT54S-E3-08" SOT95P248X115-3N 100,68 r180 top
D34 "BAT54S-E3-08" SOT95P248X115-3N 107.7,61.3 r0 top
JP1 "TSW-102-07-L-S" CON-M-THT-TSW-102-07-L-S 65,4.57 r270 top
L1 "BLM18PG600" INDC1608N 7,29.1 r180 top
L2 "BLM18KG102" INDC1608N 88.3,55.5 r180 top
L3 "4.7uH" XAL4030-472ME 58.5,72.1 r270 top
L4 "BLM18KG102" INDC1608N 88.3,54 r0 top
L5 "BLM21PG300SN1" INDC2009N 27,25.7 r270 top
L6 "XAL4030-682MEC" XFL4020 30.5,26 r270 top
MH1 "Mounting Hole for M3" MOUNTING-HOLE_M3_L 15,4 r0 top
MH2 "Mounting Hole for M3" MOUNTING-HOLE_M3_L 116.5,4 r0 top
MH3 "Mounting Hole for M3" MOUNTING-HOLE_M3_L 15,83 r0 top
MH4 "Mounting Hole for M3" MOUNTING-HOLE_M3_L 116.5,83 r0 top
Q1 "BCR198W" SOT323-3AN 95,82.2 r0 top
Q2 "BCM857BS" SOT363-6M 49,75.8 r0 top
Q3 "IRLML6402" SOT95P237X112-3N-2-V 52.5,76 r0 top
Q4 "IRLML6402" SOT95P237X112-3N-2-V 52.5,71.7 r0 top
Q5 "BCM857BS" SOT363-6M 49,71.5 r0 top
Q6 "IRLML6402" SOT95P237X112-3N-2-V 52.5,67.4 r0 top
Q7 "BCM857BS" SOT363-6M 49,67.2 r0 top
Q8 "BCR198W" SOT323-3AN 95,79.1 r0 top
Q9 "BCR198W" SOT323-3AN 95,7.6 r0 top
Q10 "BCR198W" SOT323-3AN 95,3.1 r0 top
R1 "0R" RESC1005N 77.5,41.5 r270 top
R2 "0R" RESC1005N 72.6,44.1 r90 top
R3 "0R" RESC1005X03N 64,33.5 r0 top
R4 "0R" RESC1005X03N 109,80 r180 top
R5 "4.7k" RESC1609X50N 44,6.8 r180 top
R6 "10k" POT-THT-PTV09A-4020U 50.5,21.4 r90 top
R7 "10k" POT-THT-PTV09A-4020U 62.9,21.4 r90 top locked
R8 "0R" RESC1005X03N 78.5,38.5 r180 top
R9 "100R" RESC1005X40N-1 44.6,32.4 r90 top
R10 "100R" RESC1005X40N-1 70.5,29 r0 top
R11 "0R" RESC1005X03N 86,30.5 r0 top
R12 "0R" RESC1005X03N 88.5,30.5 r0 top
R13 "0R" RESC1005X03N 109,78.8 r180 top
R14 "10k" RESC1005X40N 65.6,44.7 r180 top
R15 "0R" RESC1005X03N 86,32.5 r0 top
R16 "1k" RESC1005X40N 107.1,49.8 r0 top
R17 "0R" RESC1005X03N 90.9,30.5 r0 top
R18 "5.1k" RESC1609X50N 14.2,37 r180 top
R19 "22R" RESC1005X40N 14.7,33.5 r270 top
R20 "22R" RESC1005X40N 13.5,33.5 r270 top
R21 "5.1k" RESC1609X50N 11.5,29.5 r0 top
R22 "4.7k" RESC1005X40N-1 7.802,19.802 r270 top
R23 "510R" RESC1005X40N 25.1,18 r90 top
R24 "10k" RESC1005X40N 8.902,19.802 r90 top
R25 "0R" RESC1005X03N 86,31.5 r0 top
R26 "0R" RESC1005X03N 96.5,31.5 r0 top
R27 "100k" RESC1005X40N 24.2,21.1 r0 top
R28 "1k" RESC1005X40N 117.3,57.8 r180 top
R29 "1k" RESC1005X40N 109.4,56.6 r180 top
R30 "1k" RESC1005X40N 117.3,44 r180 top
R31 "1k" RESC1005X40N 109,44.1 r0 top
R32 "100R" RESC1005X40N 117.3,26.2 r180 top
R33 "100R" RESC1005X40N 117.3,29.9 r0 top
R34 "100k" RESC1005X40N 117.3,56.8 r0 top
R35 "100k" RESC1005X40N 117.3,42.9 r0 top
R36 "20k" RESC1005X40N 117.3,27.3 r0 top
R37 "20k" RESC1005X40N 117.3,28.9 r0 top
R38 "100k" RESC1005X40N 109,45.2 r0 top
R39 "200k" RESC1005X40N 109.4,57.9 r180 top
R40 "1k" RESC1005X40N 90,62.1 r0 top
R41 "1k" RESC1005X40N 107,55 r0 top
R42 "1k" RESC1005X40N 86.8,67.5 r180 top
R43 "1k" RESC1005X40N 96.1,53.7 r180 top
R44 "1k" RESC1005X40N 81.5,67.5 r180 top
R45 "1k" RESC1005X40N 96.1,50.2 r180 top
R46 "1k" RESC1005X40N 81.5,60 r0 top
R47 "0R" RESC1005X03N 122.5,2.5 r180 top
R48 "2.2k" RESC1005X40N 18.1,77.1 r0 top
R49 "2.2k" RESC1005X40N 20.8,77.1 r0 top
R50 "100k" RESC1005X40N 54.2,6.8 r0 top
R51 "1k" RESC1005X40N 58.4,6.8 r0 top
R52 "10k" RESC1005X40N 45.7,72.5 r0 top
R53 "4.7k" RESC1609X50N 41.5,17.1 r0 top
R54 "100k" RESC1005X40N 45.7,71.5 r180 top
R55 "1k" RESC1005X40N 104.5,60.5 r180 top
R56 "0R" RESC1005X03N 88.5,32.5 r180 top
R57 "1k" RESC1005X40N 106,68 r0 top
R58 "0R" RESC1005X03N 90.9,33.5 r180 top
R59 "1k" RESC1005X40N 95.5,67.7 r180 top
R60 "0R" RESC1005X03N 88.5,31.5 r180 top
R61 "1k" RESC1005X40N 98.5,60.4 r0 top
R62 "0R" RESC1005X03N 90.9,32.5 r180 top
R63 "10k" RESC1005X40N 45.7,76.8 r0 top
R64 "100k" RESC1005X40N 45.7,75.8 r180 top
R65 "10k" RESC1005X40N 45.7,74.8 r0 top
R66 "10k" RESC1005X40N 45.7,70.5 r0 top
R67 "10k" RESC1005X40N 45.7,66.2 r0 top
R68 "100k" RESC1005X40N 45.7,67.2 r180 top
R69 "10k" RESC1005X40N 45.7,68.2 r0 top
R70 "10k" RESC1005X40N 48.5,56 r180 top
R71 "0R" RESC1005X03N 79.1,55 r90 top
R72 "0R" RESC1005X03N 93.5,31.4 r0 top
R73 "120R" RESC3216X60N 20,7.5 r90 top
R74 "0R" RESC1005X03N 93.5,32.5 r180 top
R75 "10k" RESC1005X40N 72.2,66.6 r90 top
R76 "0R" RESC1005X03N 96.5,33.5 r180 top
R77 "1.96k" RESC1005X40N 71.2,66.6 r270 top
R78 "0R" RESC1005X03N 71.7,72.6 r0 top
R79 "0R" RESC1005X03N 67.7,70.9 r180 top
R80 "0R" RESC1005X03N 67.7,60.2 r180 top
R81 "0R" RESC1005X03N 88.5,34.5 r180 top
R82 "0R" RESC1005X03N 90.9,34.5 r180 top
R83 "0R" RESC1005X03N 93.5,34.5 r180 top
R84 "120R" RESC1005X40N 71.7,71.3 r180 top
R85 "120R" RESC1005X40N 67.7,69.7 r180 top
R86 "120R" RESC1005X40N 67.7,59.3 r180 top
R87 "0R" RESC1005X03N 96.5,34.7 r180 top
R88 "0R" RESC1005X03N 88.5,33.5 r180 top
R89 "0R" RESC1005X03N 90.9,31.5 r180 top
R90 "0R" RESC1005X03N 93.5,33.5 r180 top
R91 "10k" RESC1005X40N 74.2,18.5 r90 top
R92 "0R" RESC1005X03N 96.5,32.5 r180 top
R93 "1.96k" RESC1005X40N 73.2,18.5 r270 top
R94 "0R" RESC1005X03N 72.2,18.5 r270 top
R95 "0R" RESC1005X03N 72.2,10.5 r90 top
R96 "0R" RESC1005X03N 73.2,10.5 r90 top
R97 "0R" RESC1005X03N 86,33.5 r180 top
R98 "0R" RESC1005X03N 97.9,45 r180 top
R99 "10k" RESC1005X40N 77.5,49.5 r180 top
R100 "120R" RESC1005X40N 71.2,18.5 r270 top
R101 "120R" RESC1005X40N 71.2,10.5 r90 top
R102 "120R" RESC1005X40N 74.2,10.5 r90 top
R103 "0R" RESC1005X03N 18.5,59.6 r180 top
R104 "0R" RESC1005X03N 21,59.6 r180 top
R105 "1.96k" RESC1005X40N 96.1,51.1 r180 top
R106 "10k" RESC1005X40N 63.5,73.6 r0 top
R107 "1k" RESC1005X40N 58.1,83.1 r180 top
R108 "0R" RESC1005X03N 63.5,74.5 r180 top
R109 "680R" RESC1608X55N-1 49.8,4 r180 top
R110 "680R" RESC1608X55N-1 58,4 r180 top
R111 "680R" RESC1608X55N-1 27.4,81.6 r0 top
R112 "680R" RESC1608X55N-1 11.5,27 r0 top
R113 "680R" RESC1608X55N-1 15.5,27 r180 top
R114 "10k" RESC1005X40N 106.3,78.8 r180 top
R115 "10k" RESC1005X40N 103.7,78.8 r180 top
R116 "10k" RESC1005X40N 100.5,78.8 r0 top
R117 "1.96k" RESC1005X40N 96.1,52.7 r180 top
R118 "1.96k" RESC1005X40N 107,56.2 r0 top
R119 "1.96k" RESC1005X40N 107.1,48.2 r0 top
R120 "10k" RESC1005X40N 101,8.2 r180 top
R121 "10k" RESC1005X40N 103.9,8.2 r180 top
R122 "10k" RESC1005X40N 106.8,8.2 r180 top
R123 "1.96k" RESC1005X40N 98.5,59.5 r0 top
R124 "1.96k" RESC1005X40N 95.5,68.8 r180 top
R125 "1.96k" RESC1005X40N 105.97,69 r0 top
R126 "100R" RESC1005X40N-1 48.5,6.8 r0 top
R127 "10k" RESC1005X40N 48.5,58.5 r180 top
R128 "10k" RESC1005X40N 56.9,55.9 r180 top
R129 "10k" RESC1005X40N 56.9,53 r180 top
R130 "10k" RESC1005X40N 56.9,61.6 r180 top
R131 "56k" RESC1005X40N 42,54.5 r90 top
R132 "18k" RESC1005X40N 42,52.5 r90 top
R133 "56k" RESC1005X40N 35.9,73.7 r180 top
R134 "33k" RESC1005X40N 37.9,73.7 r180 top
R135 "56k" RESC1005X40N 19.6,29.1 r180 top
R136 "1.96k" RESC1005X40N 104.5,59.5 r180 top
R137 "1.96k" RESC1005X40N 81.5,59 r0 top
R138 "1.96k" RESC1005X40N 81.5,68.5 r180 top
R139 "1.96k" RESC1005X40N 86.8,68.5 r180 top
R140 "10k" RESC1005X40N 119.5,16.8 r180 top
R141 "2.2k" RESC1005X40N 119.5,9.9 r180 top
R142 "2.2k" RESC1005X40N 119.5,11.4 r180 top
R143 "10k" RESC1005X40N 119.5,19.2 r180 top
R144 "10k" RESC1005X40N 119.5,18 r180 top
R145 "10k" RESC1005X40N 65.6,32.3 r0 top
R146 "33k" RESC1005X40N 19.6,28 r0 top
R147 "1.96k" RESC1005X40N 92,62.1 r180 top
R148 "1k" RESC1005X40N 101.5,37.2 r180 top
R149 "1.96k" RESC1005X40N 101.5,38.4 r180 top
R150 "1k" RESC1005X40N 48,53.2 r0 top
R151 "120R" RESC1005X40N 106.3,80 r0 top
R152 "1k" RESC1005X40N 48,49.5 r0 top
R153 "120R" RESC1005X40N 103.7,80 r180 top
R155 "120R" RESC1005X40N 100.5,79.9 r180 top
R157 "120R" RESC1005X40N 101,7.1 r0 top
R159 "120R" RESC1005X40N 103.9,7.1 r0 top
R160 "120R" RESC1005X40N 106.8,7.1 r0 top
R162 "3.3k" RESC1005X40N 119.5,40.2 r90 top
R163 "3.3k" RESC1005X40N 119.5,27.3 r0 top
SW1 "FSM2JSMA" FSM2JSMA 46.2,12.5 r180 top
SW2 "FSM2JSMA" FSM2JSMA 59,12.5 r180 top
SW3 "219-3LPST" 219-3LP 52.8,42.2 r90 top locked
TP1 "" TP_RD_SMD_1MM 30.5,3 r0 top
TP2 "" TP_RD_SMD_1MM 6,27 r90 top
TP3 "" TP_RD_SMD_1MM 6,19.5 r90 top
TP4 "" TP_RD_SMD_1MM 12.5,13 r90 top
TP5 "" TP_RD_SMD_1MM 45.6,81 r90 top
TP6 "" TP_RD_SMD_1MM 43,64.5 r90 top
TP7 "" TP_RD_SMD_1MM 24,46.3 r90 top
TP8 "" TP_RD_SMD_1MM 43,63.2 r90 top
TP9 "" TP_RD_SMD_1MM 43,61.8 r90 top
U1 "PSC3M5FDS2AFQ1" QFP50P1400X1400X160-81N 88.35,43.5 r0 top locked
U2 "TLS205B0EJV" SOIC127P600X170-9N-3-V1 36,78.4 r90 top
U3 "AM26LV32EIPWR" SOP65P640X120-16N-2 67.9,64.65 r270 top
U4 "2DIB1400F" SOIC127P600X175-8N-22-V1 34.8,7.5 r0 top
U5 "AD8618ARUZ" SOP65P640X120-14N-0 101.5,52 r180 top
U6 "AM26LV32EIPWR" SOP65P640X120-16N-2 71.85,14.8 r0 top
U7 "IFX_XMC4200-Q48K256 BA" QFN50P700X700X90-49N-8 18.5,20 r0 top locked
U8 "TLS205B0EJV" SOIC127P600X170-9N-3-V1 20.8,33.6 r90 top
U9 "AD8618ARUZ" SOP65P640X120-14N-0 101.5,63.6 r180 top
U10 "Si8662BB" SOIC127P600-16N 34.7,18.4 r0 top locked
U11 "AD8618ARUZ" SOP65P640X120-14N-0 84.2,63.6 r180 top
U12 "74LVC1G126DCK" SOT353-5N 41.5,19.2 r0 top
U13 "TLE9371SJ" SOIC127P602X173-8N 26,7.5 r180 top
U14 "TLS205B0EJV" SOIC127P600X170-9N-3-V1 38.7,51.2 r270 top locked
U15 "TS5A23157DGSR" VSSOP50P490X110-10N 41.5,24 r90 top locked
U16 "TLS4125D0EPV50" SOP65P600X115-15N 59.1,78.4 r270 top
U17 "TS5A23157DGSR" VSSOP50P490X110-10N 52.8,57.2 r180 top locked
U18 "TS5A23157DGSR" VSSOP50P490X110-10N 52.8,52 r180 top locked
U19 "TS5A23157DGSR" VSSOP50P490X110-10N 52.8,62.5 r180 top locked
U20 "5V / 7V" IES0205S05 34.7,34.8 r0 top locked
U21 "AD8615AUJZ-R2" SOT95P280X100-5N-0 102.5,34.5 r0 top
X1 "FTSH-110-01-L-DV-K" CON-M-SMD-FTSH-110-01-L-DV-K 88.3,25.5 r90 top locked
X2 "N2510-6002RB" CON-M-THT-N2510-6002RB 82.12,82.1 r90 top
X3 "1725685" CON-TER-THT-1725685 104.5,83.9 r180 top
X4 "N2510-6002RB" CON-M-THT-N2510-6002RB 82.12,4.57 r270 top
X7 "1725685" CON-TER-THT-1725685 104.5,3.1 r0 top locked
X10 "USB-C" 632723300011 5.7,35.5 r270 top locked
X11 "FTSH-106-01-L-DV-K" CON-M-SMD-FTSH-106-01-L-DV-K 64,38 r90 top locked
X12 "FTSH-105-01-L-DV-K-A-TR" CON-M-SMD-FTSH-105-01-L-DV-K-A-TR 64,49.5 r90 top locked
X13 "61300511121" CON-M-THT-61300511121 2.6,21.97 r90 top
X14 "826936-4" CON-M-THT-826936-4 2.6,8 r90 top
X15 "FX2-100S-1.27DSL_71_" FX2100S127DSL71 129.5,43.5 r90 top locked
X16 "HTSW-115-07-G-D" HDRV30W64P254_2X15_3810X502X838B 96.856,12.192 r90 top locked
X17 "HTSW-115-07-G-D" HDRV30W64P254_2X15_3810X502X838B 96.856,73.152 r90 top locked
X18 "mikroBUS" "MIKROBUS HOST CONN." 7.54,51.64 r90 top locked
X19 "Header 16X2" HDRV32W64P254_2X16_4070X508X838B 113.366,42.672 r180 top locked value=TSW-116-07-L-D
X20 "HTSW-103-07-L-S" CON-M-THT-HTSW-103-07-L-S 33,64.5 r90 top
X22 "W1*1" HDR1X1 9.1,13.7 r0 top
X23 "W1*1" HDR1X1 25.5,39.5 r0 top
X24 "W1*1" HDR1X1 66,83 r0 top
X25 "W1*1" HDR1X1 73.22,25.74 r0 top
X26 "W1*1" HDR1X1 33,51.64 r0 top
X27 "W1*1" HDR1X1 103.82,40.64 r0 top
X28 "TSW-102-07-L-S" CON-M-THT-TSW-102-07-L-S 21.5,3 r180 top
X29 "HTSW-103-07-L-S" CON-M-THT-HTSW-103-07-L-S 53.1,35.2 r180 top
X30 "TSW-102-07-L-S" CON-M-THT-TSW-102-07-L-S 7.5,4 r270 top
Y1 "16MHZ" Oscillator_3225 75.5,38.2 r180 top
Y2 "12MHz" Oscillator_3225 24.9,14.8 r180 top value="NX3225SA 12MHZ AT-W"
Y3 "32.768kHz" XTAL-SMD-ABS07 75,41.5 r180 top

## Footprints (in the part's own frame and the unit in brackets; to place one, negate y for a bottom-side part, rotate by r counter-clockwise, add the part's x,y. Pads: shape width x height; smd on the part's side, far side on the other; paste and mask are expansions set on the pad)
219-3LP [mm] "Dip Switch, RM 2.54, 4 polig"
  rect 1.13x2.44 smd: 1(-2.54,-4.3) 2(0,-4.3) 3(2.54,-4.3) 4(2.54,4.3) 5(0,4.3) 6(-2.54,4.3)
  silkscreen extent -4.53,-6.6 4.53,3.4, body extent -4.54,-5.41 4.54,5.41, height 3.95
632723300011 [mm] "USB 3.1 Type C Receptacle Horizontal THR/SMT"
  rect 0.3x1.2 smd: A1(-2.75,5.93) A2(-2.25,5.93) A3(-1.75,5.93) A4(-1.25,5.93) A5(-0.75,5.93) A6(-0.25,5.93) A7(0.25,5.93) A8(0.75,5.93) A9(1.25,5.93) A10(1.75,5.93) A11(2.25,5.93) A12(2.75,5.93)
  round 0.65 hole 0.4: B1(2.8,4.68) B2(2.4,3.98) B3(1.6,3.98) B4(1.2,4.68) B5(0.8,3.98) B6(0.4,4.68) B7(-0.4,4.68) B8(-0.8,3.98) B9(-1.2,4.68) B10(-1.6,3.98) B11(-2.4,3.98) B12(-2.8,4.68) G1(2,4.68) G2(-2,4.68)
  oval 1x1.6 hole 0.6 slot 1.2 at 90 deg: S1(-4.27,-1.2) S2(-4.27,3.53) S3(4.27,3.53) S4(4.27,-1.2)
  rect 0.2x1 smd: S5(0,1.35) S6(0,-1.75)
  silkscreen extent -4.37,-4.45 4.34,5, body extent -4.37,-5.6 4.37,6.19, height 3.05
CAPC1005X55N-0 [mm] "Capacitor,non-polarized,Chip;1.00mm L X 0.50mm W X 0.55mm H"
  rect 0.65x0.62 smd paste+0 mask+0: 1(-0.44,0) 2(0.44,0)
  body extent -0.5,-0.25 0.5,0.25, height 0.55
CAPC1005X60N [mm] "Capacitor,non-polarized,Chip;1.00mm L X 0.50mm W X 0.60mm H"
  rect 0.62x0.64 smd paste+0 mask+0: 1(-0.46,0) 2(0.46,0)
  body extent -0.5,-0.25 0.5,0.25, height 0.6
CAPC1608X90N-1 [mm] "Capacitor,non-polarized,Chip;1.60mm L X 0.80mm W X 0.90mm H"
  rect 0.9x0.95 smd paste+0 mask+0: 1(-0.75,0) 2(0.75,0)
  body extent -0.8,-0.4 0.8,0.4, height 0.9
CAPC2013X145N-3 [mm] "Capacitor,non-polarized,Chip;2.00mm L X 1.25mm W X 1.45mm H"
  rect 1.15x1.45 smd paste+0 mask+0: 1(-0.9,0) 2(0.9,0)
  body extent -1,-0.63 1,0.63, height 1.45
CAPC3216X180N [mm] "Capacitor,non-polarized,Chip;3.20mm L X 1.60mm W X 1.80mm H"
  rect 1.2x1.8 smd paste+0 mask+0: 1(-1.45,0) 2(1.45,0)
  silkscreen extent -0.5,-0.8 0.5,0.8, body extent -1.6,-0.8 1.6,0.8, height 1.8
CON-M-SMD-FTSH-105-01-L-DV-K-A-TR [mm] "Header, vertical, 1.27mm pitch; 10 pins, 2 rows, 5 pins per row, 6.35mm L X 5.08mm W X 6.223mm H body"
  rect 2.79x0.74 smd paste+0 mask+0: 1(-2.035,2.54) 2(2.035,2.54) 3(-2.035,1.27) 4(2.035,1.27) 5(-2.035,0) 6(2.035,0) 7(-2.035,-1.27) 8(2.035,-1.27) 9(-2.035,-2.54) 10(2.035,-2.54)
  round 0 hole 0.97 unplated paste+0 mask+0: ""(0,1.905) ""(0,-1.905)
  silkscreen extent -4.62,-3.7 4,3.7, body extent -2.92,-3.14 2.92,3.14, height 6.12
CON-M-SMD-FTSH-106-01-L-DV-K [mm] "Connector, SMD, 1.27 mm pitch, 12 pin, 3.43 mm L X 7.62 mm W X 6.38 mm H body"
  rect 2.79x0.74 smd mask+0: 1(-2.035,3.175) 2(2.035,3.175) 3(-2.035,1.905) 4(2.035,1.905) 5(-2.035,0.635) 6(2.035,0.635) 7(-2.035,-0.635) 8(2.035,-0.635) 9(-2.035,-1.905) 10(2.035,-1.905) 11(-2.035,-3.175) 12(2.035,-3.175)
  silkscreen extent -4.6,-4 3.9,4, body extent -2.92,-3.81 2.92,3.81, height 6.12
CON-M-SMD-FTSH-110-01-L-DV-K [mm] "Header, Vertical, 1.27mm Pitch; 20 Pins, 2 rows, 10 Pins per row, 12.7mm L X 5.08mm W X 6.375mm H body"
  rect 2.79x0.74 smd paste+0 mask+0: 1(-2.035,5.715) 2(2.035,5.715) 3(-2.035,4.445) 4(2.035,4.445) 5(-2.035,3.175) 6(2.035,3.175) 7(-2.035,1.905) 8(2.035,1.905) 9(-2.035,0.635) 10(2.035,0.635) 11(-2.035,-0.635) 12(2.035,-0.635) 13(-2.035,-1.905) 14(2.035,-1.905) 15(-2.035,-3.175) 16(2.035,-3.175) 17(-2.035,-4.445) 18(2.035,-4.445) 19(-2.035,-5.715) 20(2.035,-5.715)
  silkscreen extent -4.72,-7 4,7, body extent -2.92,-6.35 2.92,6.35, height 6.12
CON-M-THT-826936-4 [mm] "Header,vertical,2.54mm pitch;0.63mm lead width,4 pins,1 row,4 pins per row,10.16mm L X 2.5mm W X 8.6mm H body"
  rect 1.7x1.7 hole 1 paste+0 mask+0: 1(-3.81,0)
  round 1.7 hole 1 paste+0 mask+0: 2(-1.27,0) 3(1.27,0) 4(3.81,0)
  silkscreen extent -5.8,-1.25 5.1,1.25, body extent -5.08,-1.25 5.08,1.25, height 8.6
CON-M-THT-61300511121 [mm] "Connector, THT; 2.54mm Pitch, 5 Pins, 12.70 mm L X 2.54 mm W X 8.89 mm H body"
  rect 1.7x1.7 hole 1.1 paste+0 mask+0: 1(-5.08,0)
  round 1.7 hole 1.1 paste+0 mask+0: 2(-2.54,0) 3(0,0) 4(2.54,0) 5(5.08,0)
  silkscreen extent -7.17,-1.3 6.4,1.3, body extent -6.35,-1.27 6.35,1.27, height 8.54
CON-M-THT-HTSW-103-07-L-S [mm] "Header,vertical,2.54mm pitch;0.64mm lead width,3 pins,1 row,3 pins per row,7.62mm L X 2.48mm W X 8.38mm H body"
  rect 1.7x1.7 hole 1.1 paste+0 mask+0: 1(-2.54,0)
  round 1.7 hole 1.1 paste+0 mask+0: 2(0,0) 3(2.54,0)
  silkscreen extent -4.51,-1.25 3.86,1.25, body extent -3.81,-1.27 3.81,1.27, height 8.4
CON-M-THT-N2510-6002RB [mm] "Connector, THT, 2.54 mm pitch, 10 pin, 8.59 mm L X 20.02 mm W X 10.04 mm H body"
  rect 1.49x1.49 hole 0.89 paste+0 mask+0: 1(-1.27,5.08)
  round 1.49 hole 0.89 paste+0 mask+0: 2(1.27,5.08) 3(-1.27,2.54) 4(1.27,2.54) 5(-1.27,0) 6(1.27,0) 7(-1.27,-2.54) 8(1.27,-2.54) 9(-1.27,-5.08) 10(1.27,-5.08)
  silkscreen extent -4.87,-10.1 4.6,10.1, body extent -4.07,-10.01 4.52,10.01, height 10.04
CON-M-THT-TSW-102-07-L-S [mm] "Header,vertical,2.54mm pitch;0.64mm lead width,2 pins,1 row,2 pins per row,5.08mm L X 2.54mm W X 8.636mm H body"
  rect 1.7x1.7 hole 1.1 paste+0 mask+0: 1(-1.27,0)
  round 1.7 hole 1.1 paste+0 mask+0: 2(1.27,0)
  silkscreen extent -3.59,-1.6 2.8,1.6, body extent -2.67,-1.27 2.54,1.27, height 8.38
CON-TER-THT-1725685 [mm] "Terminal Block, THT, 2.54 mm pitch, 5 pin, 13.16 mm L X 6.20 mm W X 8.65 mm H body"
  rect 1.7x1.7 hole 1.1 paste+0 mask+0: 1(-5.08,0)
  round 1.7 hole 1.1 paste+0 mask+0: 2(-2.54,0) 3(0,0) 4(2.54,0) 5(5.08,0)
  silkscreen extent -7.12,-3.1 6.6,3.1, body extent -6.58,-3.1 6.58,3.1, height 8.5
FIDUCIAL_ROUND_1.5MM [mm] "Fiducial Round 1.5mm Copper, 3mm Soldermask"
  round 1.5 smd paste-10 mask+0.75: ADJ(0,0)
  Top Layer keep-out circle w0: c0,0 r1.5
FSM2JSMA [mm] "Switch,Push button ,4.5mm Pitch,Vertical, 6mm L X 6mm W X 5.25mm H body"
  rect 2.1x1.4 smd paste+0 mask+0: 1(-4.55,2.25) 2(4.55,2.25) 3(-4.55,-2.25) 4(4.55,-2.25)
  silkscreen extent -3,-3 3,3, body extent -5,-3 5,3, height 4.36
FX2100S127DSL71 [mm]
  rect 1.4x1.4 hole 0.9: A1(-31.115,5.31)
  round 1.4 hole 0.9: A2(-29.845,7.215) A3(-28.575,5.31) A4(-27.305,7.215) A5(-26.035,5.31) A6(-24.765,7.215) A7(-23.495,5.31) A8(-22.225,7.215) A9(-20.955,5.31) A10(-19.685,7.215) A11(-18.415,5.31) A12(-17.145,7.215) A13(-15.875,5.31) A14(-14.605,7.215) A15(-13.335,5.31) A16(-12.065,7.215) A17(-10.795,5.31) A18(-9.525,7.215) A19(-8.255,5.31) A20(-6.985,7.215) A21(-5.715,5.31) A22(-4.445,7.215) A23(-3.175,5.31) A24(-1.905,7.215) A25(-0.635,5.31) A26(0.635,7.215) A27(1.905,5.31) A28(3.175,7.215) A29(4.445,5.31) A30(5.715,7.215) A31(6.985,5.31) A32(8.255,7.215) A33(9.525,5.31) A34(10.795,7.215) A35(12.065,5.31) A36(13.335,7.215) A37(14.605,5.31) A38(15.875,7.215) A39(17.145,5.31) A40(18.415,7.215) A41(19.685,5.31) A42(20.955,7.215) A43(22.225,5.31) A44(23.495,7.215) A45(24.765,5.31) A46(26.035,7.215) A47(27.305,5.31) A48(28.575,7.215) A49(29.845,5.31) A50(31.115,7.215) B1(-31.115,1.5) B2(-29.845,3.405) B3(-28.575,1.5) B4(-27.305,3.405) B5(-26.035,1.5) B6(-24.765,3.405) B7(-23.495,1.5) B8(-22.225,3.405) B9(-20.955,1.5) B10(-19.685,3.405) B11(-18.415,1.5) B12(-17.145,3.405) B13(-15.875,1.5) B14(-14.605,3.405) B15(-13.335,1.5) B16(-12.065,3.405) B17(-10.795,1.5) B18(-9.525,3.405) B19(-8.255,1.5) B20(-6.985,3.405) B21(-5.715,1.5) B22(-4.445,3.405) B23(-3.175,1.5) B24(-1.905,3.405) B25(-0.635,1.5) B26(0.635,3.405) B27(1.905,1.5) B28(3.175,3.405) B29(4.445,1.5) B30(5.715,3.405) B31(6.985,1.5) B32(8.255,3.405) B33(9.525,1.5) B34(10.795,3.405) B35(12.065,1.5) B36(13.335,3.405) B37(14.605,1.5) B38(15.875,3.405) B39(17.145,1.5) B40(18.415,3.405) B41(19.685,1.5) B42(20.955,3.405) B43(22.225,1.5) B44(23.495,3.405) B45(24.765,1.5) B46(26.035,3.405) B47(27.305,1.5) B48(28.575,3.405) B49(29.845,1.5) B50(31.115,3.405)
  round 3.6 hole 2.4: MH1(-34.425,3.405) MH2(34.425,3.405)
  silkscreen extent -36.77,-8 36.77,8, body extent -36.78,-7.99 36.78,8.01, height 7.54
HDR1X1 [mm] "Connector; Header; 1 Position"
  rect 1.7x1.7 / inner round 1.5 / far side rect 1.7x1.7 hole 1: 1(0,0)
  silkscreen extent -1.27,-1.27 1.27,1.27, body extent -1.27,-1.27 1.27,1.27, height 11
HDRV30W64P254_2X15_3810X502X838B [mm] "Header,vertical,2.54mm pitch;0.64mm lead width,30 pins,2 rows,15 pins per row,38.10mm L X 5.02mm W X 8.38mm H body"
  rect 1.7x1.7 / inner round 1.7 / far side rect 1.7x1.7 hole 1.1 paste+0 mask+0: 1(-1.27,17.78)
  round 1.7 hole 1.1 paste+0 mask+0: 2(1.27,17.78) 3(-1.27,15.24) 4(1.27,15.24) 5(-1.27,12.7) 6(1.27,12.7) 7(-1.27,10.16) 8(1.27,10.16) 9(-1.27,7.62) 10(1.27,7.62) 11(-1.27,5.08) 12(1.27,5.08) 13(-1.27,2.54) 14(1.27,2.54) 15(-1.27,0) 16(1.27,0) 17(-1.27,-2.54) 18(1.27,-2.54) 19(-1.27,-5.08) 20(1.27,-5.08) 21(-1.27,-7.62) 22(1.27,-7.62) 23(-1.27,-10.16) 24(1.27,-10.16) 25(-1.27,-12.7) 26(1.27,-12.7) 27(-1.27,-15.24) 28(1.27,-15.24) 29(-1.27,-17.78) 30(1.27,-17.78)
  silkscreen extent -2.51,-19.05 2.51,19.69, body extent -2.54,-19.05 2.54,19.05, height 8.38
HDRV32W64P254_2X16_4070X508X838B [mm] "Header,vertical,2.54mm pitch;0.64mm lead width,32 pins,2 rows,16 pins per row,40.705mm L X 2.54mm W X 8.38mm H body"
  rect 1.7x1.7 hole 1.1 paste+0 mask+0: 1(-1.27,-19.05)
  round 1.7 hole 1.1 paste+0 mask+0: 2(1.27,-19.05) 3(-1.27,-16.51) 4(1.27,-16.51) 5(-1.27,-13.97) 6(1.27,-13.97) 7(-1.27,-11.43) 8(1.27,-11.43) 9(-1.27,-8.89) 10(1.27,-8.89) 11(-1.27,-6.35) 12(1.27,-6.35) 13(-1.27,-3.81) 14(1.27,-3.81) 15(-1.27,-1.27) 16(1.27,-1.27) 17(-1.27,1.27) 18(1.27,1.27) 19(-1.27,3.81) 20(1.27,3.81) 21(-1.27,6.35) 22(1.27,6.35) 23(-1.27,8.89) 24(1.27,8.89) 25(-1.27,11.43) 26(1.27,11.43) 27(-1.27,13.97) 28(1.27,13.97) 29(-1.27,16.51) 30(1.27,16.51) 31(-1.27,19.05) 32(1.27,19.05)
  silkscreen extent -2.54,-20.97 2.54,20.32, body extent -2.54,-20.32 2.54,20.32, height 8.38
IES0205S05 [mm] "SMD-8, 13.2mm x 8.5mm"
  rect 1x2.29 smd: 1(-3.81,-4.955) 2(-1.27,-4.955) 4(3.81,-4.955) 5(3.81,4.955) 8(-3.81,4.955)
  silkscreen extent -6.8,-6.12 6.8,5.4, body extent -6.6,-6 6.6,6, height 7.85
INDC1608N [mm] "Chip Inductor, Body 1.6x0.8mm, IPC Medium Density"
  rect 1x1 smd: 1(-0.8,0) 2(0.8,0)
  silkscreen extent -1.6,-0.4 -1.6,0.4, body extent -0.8,-0.4 0.8,0.4, height 0.9
INDC2009N [mm] "Chip Inductor, Body 2.0x0.9mm, IPC Medium Density"
  rect 1x1.2 smd: 1(-1.1,0) 2(1.1,0)
  silkscreen extent -0.2,-0.5 0.2,0.5, body extent -1,-0.6 1,0.6, height 0.95
LEDSC160X80X40-2N [mm] "LED,Side Concave;2 pin,1.60mm W X 0.80mm L X 0.40mm H"
  rect 0.8x0.8 smd paste+0 mask+0: 1(-0.75,0) 2(0.75,0)
  silkscreen extent -1.83,-0.12 -1.58,0.12, body extent -0.8,-0.4 0.8,0.4, height 0.35
LEDSC160X80X80-2N [mm] "LED,Side Concave;2 pin,1.60mm W X 0.80mm L X 0.80mm H"
  rect 0.9x0.8 smd paste+0 mask+0: 1(-0.85,0) 2(0.85,0)
  silkscreen extent -1.97,-0.12 -1.73,0.12, body extent -0.8,-0.4 0.8,0.4, height 0.8
"MIKROBUS HOST CONN." [mil]
  rect 65x65 hole 35: 1(0,0) 16(900,0)
  round 65 hole 35: 2(0,-100) 3(0,-200) 4(0,-300) 5(0,-400) 6(0,-500) 7(0,-600) 8(0,-700) 9(900,-700) 10(900,-600) 11(900,-500) 12(900,-400) 13(900,-300) 14(900,-200) 15(900,-100)
  silkscreen extent -100,-900 1000,225, body extent -49,-755 949,55, height 335
MOUNTING-HOLE_M3_L [mm] "Mounting Hole for M3, 3.2mm Hole, 6.5mm x 6.5mm Pad, Hidden 3D-Body"
  round 6.5 hole 3.2: 1(0,0)
  silkscreen extent -3.5,-3.5 3.5,3.5, body extent -3.25,-3.35 3.25,3.15, height 0.03
Oscillator_3225 [mm] "Oscillator Module, 3.2mm x 2.5mm"
  rect 1.3x1.05 smd: 1(-1.15,-0.925) 2(1.15,-0.925) 3(1.15,0.925) 4(-1.15,0.925)
  silkscreen extent -2.9,-1.7 2,1.7, body extent -1.61,-1.25 1.61,1.25, height 0.81
POT-THT-PTV09A-4020U [mm] "Potentiometer; THT, 2.5 mm pitch, 11.80 mm L X 10 mm W X 20.5 mm H body"
  rect 1.6x1.6 hole 1: 1(-3.5,2.5)
  round 1.6 hole 1: 2(-3.5,0) 3(-3.5,-2.5)
  round 3.124 hole 2.2: MH1(3.5,4.4) MH2(3.5,-4.4)
  silkscreen extent -4.16,-5 9,5, body extent -3.63,-5.7 9,5.7, height 20.5
QFN50P700X700X90-49N-8 [mm] "QFN,0.50mm pitch,square;48 pin,7.00mm L X 7.00mm W X 0.90mm H body (w/thermal tab)"
  rect 0.8x0.3 smd paste+0 mask+0: 1(-3.5,2.75) 2(-3.5,2.25) 3(-3.5,1.75) 4(-3.5,1.25) 5(-3.5,0.75) 6(-3.5,0.25) 7(-3.5,-0.25) 8(-3.5,-0.75) 9(-3.5,-1.25) 10(-3.5,-1.75) 11(-3.5,-2.25) 12(-3.5,-2.75) 25(3.5,-2.75) 26(3.5,-2.25) 27(3.5,-1.75) 28(3.5,-1.25) 29(3.5,-0.75) 30(3.5,-0.25) 31(3.5,0.25) 32(3.5,0.75) 33(3.5,1.25) 34(3.5,1.75) 35(3.5,2.25) 36(3.5,2.75)
  rect 0.3x0.8 smd paste+0 mask+0: 13(-2.75,-3.5) 14(-2.25,-3.5) 15(-1.75,-3.5) 16(-1.25,-3.5) 17(-0.75,-3.5) 18(-0.25,-3.5) 19(0.25,-3.5) 20(0.75,-3.5) 21(1.25,-3.5) 22(1.75,-3.5) 23(2.25,-3.5) 24(2.75,-3.5) 37(2.75,3.5) 38(2.25,3.5) 39(1.75,3.5) 40(1.25,3.5) 41(0.75,3.5) 42(0.25,3.5) 43(-0.25,3.5) 44(-0.75,3.5) 45(-1.25,3.5) 46(-1.75,3.5) 47(-2.25,3.5) 48(-2.75,3.5)
  rect 5.25x5.25 smd paste+0 mask+0: 49(0,0)
  silkscreen extent -4.62,-3.5 3.5,3.5, body extent -3.5,-3.5 3.5,3.5, height 0.9
QFP50P1400X1400X160-81N [mm] "QFP,0.50mm pitch,square;80 pin,12.00mm L X 12.00mm W X 1.60mm H body (w/thermal tab)"
  rect 1.5x0.3 smd paste+0 mask+0: 1(-6.7,4.75) 2(-6.7,4.25) 3(-6.7,3.75) 4(-6.7,3.25) 5(-6.7,2.75) 6(-6.7,2.25) 7(-6.7,1.75) 8(-6.7,1.25) 9(-6.7,0.75) 10(-6.7,0.25) 11(-6.7,-0.25) 12(-6.7,-0.75) 13(-6.7,-1.25) 14(-6.7,-1.75) 15(-6.7,-2.25) 16(-6.7,-2.75) 17(-6.7,-3.25) 18(-6.7,-3.75) 19(-6.7,-4.25) 20(-6.7,-4.75) 41(6.7,-4.75) 42(6.7,-4.25) 43(6.7,-3.75) 44(6.7,-3.25) 45(6.7,-2.75) 46(6.7,-2.25) 47(6.7,-1.75) 48(6.7,-1.25) 49(6.7,-0.75) 50(6.7,-0.25) 51(6.7,0.25) 52(6.7,0.75) 53(6.7,1.25) 54(6.7,1.75) 55(6.7,2.25) 56(6.7,2.75) 57(6.7,3.25) 58(6.7,3.75) 59(6.7,4.25) 60(6.7,4.75)
  rect 0.3x1.5 smd paste+0 mask+0: 21(-4.75,-6.7) 22(-4.25,-6.7) 23(-3.75,-6.7) 24(-3.25,-6.7) 25(-2.75,-6.7) 26(-2.25,-6.7) 27(-1.75,-6.7) 28(-1.25,-6.7) 29(-0.75,-6.7) 30(-0.25,-6.7) 31(0.25,-6.7) 32(0.75,-6.7) 33(1.25,-6.7) 34(1.75,-6.7) 35(2.25,-6.7) 36(2.75,-6.7) 37(3.25,-6.7) 38(3.75,-6.7) 39(4.25,-6.7) 40(4.75,-6.7) 61(4.75,6.7) 62(4.25,6.7) 63(3.75,6.7) 64(3.25,6.7) 65(2.75,6.7) 66(2.25,6.7) 67(1.75,6.7) 68(1.25,6.7) 69(0.75,6.7) 70(0.25,6.7) 71(-0.25,6.7) 72(-0.75,6.7) 73(-1.25,6.7) 74(-1.75,6.7) 75(-2.25,6.7) 76(-2.75,6.7) 77(-3.25,6.7) 78(-3.75,6.7) 79(-4.25,6.7) 80(-4.75,6.7)
  rect 5.6x5.6 smd paste+0 mask+0: 81(0,0)
  silkscreen extent -7.32,-5.6 5.6,5.6, body extent -7,-7 7,7, height 1.61
RESC1005N [mm] "Chip Resistor, Body 1.1x0.5mm, IPC Medium Density"
  rect 0.8x0.7 smd: 1(-0.6,0) 2(0.6,0)
  body extent -0.5,-0.25 0.5,0.25, height 0.34
RESC1005X03N [mm] "Resistor,Chip;1.00mm L X 0.50mm W X 0.40mm H"
  rect 0.6x0.6 smd paste+0 mask+0: 1(-0.45,0) 2(0.45,0)
  body extent -0.5,-0.25 0.5,0.25, height 0.4
RESC1005X40N [mm] "Resistor,Chip;1.00mm L X 0.50mm W X 0.40mm H"
  rect 0.58x0.62 smd paste+0 mask+0: 1(-0.47,0) 2(0.47,0)
  body extent -0.5,-0.25 0.5,0.25, height 0.35
RESC1005X40N-1 [mm] "Resistor,Chip;1.00mm L X 0.50mm W X 0.40mm H"
  rect 0.6x0.62 smd paste+0 mask+0: 1(-0.46,0) 2(0.46,0)
  body extent -0.5,-0.25 0.5,0.25, height 0.4
RESC1608X55N-1 [mm] "Resistor,Chip;1.60mm L X 0.80mm W X 0.55mm H"
  rect 0.8x0.95 smd paste+0 mask+0: 1(-0.8,0) 2(0.8,0)
  body extent -0.8,-0.4 0.8,0.4, height 0.55
RESC1609X50N [mm] "Resistor,Chip;1.575mm L X 0.85mm W X 0.50mm H"
  rect 0.72x0.99 smd paste+0 mask+0: 1(-0.69,0) 2(0.69,0)
  body extent -0.79,-0.42 0.79,0.42, height 0.5
RESC3216X60N [mm]
  rect 1.05x1.8 smd paste+0 mask+0: 1(-1.5,0) 2(1.5,0)
  silkscreen extent -0.6,-0.8 0.6,0.8, body extent -1.6,-0.8 1.6,0.8, height 0.55
SOD2513X110N [mm] "SOD;1.75mm W X 1.30mm L X 1.10mm H body"
  rect 0.85x0.5 smd paste+0 mask+0: 1(-1.3,0) 2(1.3,0)
  silkscreen extent -2.4,-0.65 0.9,0.65, body extent -1.24,-0.6 1.26,0.65, height 1.2
SOIC127P600-16N [mm] "SOIC, 16-Leads, Body 9.9x3.9mm, Pitch 1.27mm, IPC Medium Density"
  oval 2.2x0.6 smd: 1(-2.4,4.445) 2(-2.4,3.175) 3(-2.4,1.905) 4(-2.4,0.635) 5(-2.4,-0.635) 6(-2.4,-1.905) 7(-2.4,-3.175) 8(-2.4,-4.445) 9(2.4,-4.445) 10(2.4,-3.175) 11(2.4,-1.905) 12(2.4,-0.635) 13(2.4,0.635) 14(2.4,1.905) 15(2.4,3.175) 16(2.4,4.445)
  silkscreen extent -2.55,-5 0.9,5.49, body extent -2.9,-4.9 2.9,4.9, height 1.75
SOIC127P600X170-9N-3-V1 [mm] "SOIC,1.27mm pitch;8 pin,3.90mm W X 4.90mm L X 1.70mm H body (w/thermal tab)"
  rect 1.31x0.65 smd paste+0 mask+0: 1(-2.845,1.905) 2(-2.845,0.635) 3(-2.845,-0.635) 4(-2.845,-1.905) 5(2.845,-1.905) 6(2.845,-0.635) 7(2.845,0.635) 8(2.845,1.905)
  rect 2.65x3 smd paste-1.5 mask+0: 9(0,0)
  silkscreen extent -3.36,-2.5 1.6,2.9, body extent -3,-2.45 3,2.45, height 1.71
SOIC127P600X175-8N-22-V1 [mm] "SOIC,1.27mm pitch;8 pin,3.90mm W X 4.90mm L X 1.75mm H body"
  rect 1.47x0.65 smd paste+0 mask+0: 1(-2.77,1.905) 2(-2.77,0.635) 3(-2.77,-0.635) 4(-2.77,-1.905) 5(2.77,-1.905) 6(2.77,-0.635) 7(2.77,0.635) 8(2.77,1.905)
  silkscreen extent -3.37,-2.5 1.7,2.9, body extent -3,-2.5 3,2.5, height 1.75
SOIC127P602X173-8N [mm] "SOIC,1.27mm pitch;8 pin,3.899mm W X 4.889mm L X 1.727mm H body"
  rect 1.6x0.6 smd paste+0 mask+0: 1(-2.7,1.905) 2(-2.7,0.635) 3(-2.7,-0.635) 4(-2.7,-1.905) 5(2.7,-1.905) 6(2.7,-0.635) 7(2.7,0.635) 8(2.7,1.905)
  silkscreen extent -3.38,-2.45 1.58,2.87, body extent -3.01,-2.44 3.01,2.44, height 1.73
SOP65P600X115-15N [mm] "SOP,0.65mm pitch;14 pin,3.90mm W X 4.90mm L X 1.15mm H body (w/thermal tab)"
  rect 1.55x0.45 smd paste+0 mask+0: 1(-2.7,1.95) 2(-2.7,1.3) 3(-2.7,0.65) 4(-2.7,0) 5(-2.7,-0.65) 6(-2.7,-1.3) 7(-2.7,-1.95) 8(2.7,-1.95) 9(2.7,-1.3) 10(2.7,-0.65) 11(2.7,0) 12(2.7,0.65) 13(2.7,1.3) 14(2.7,1.95)
  rect 2.75x4.1 smd paste+0 mask+0: 15(0,0)
  silkscreen extent -3.32,-2.45 1.55,2.83, body extent -3,-2.45 3,2.45, height 1.16
SOP65P640X120-14N-0 [mm] "SOP,0.65mm pitch;14 pin,4.40mm W X 5.00mm L X 1.20mm H body"
  rect 1.5x0.45 smd paste+0 mask+0: 1(-2.9,1.95) 2(-2.9,1.3) 3(-2.9,0.65) 4(-2.9,0) 5(-2.9,-0.65) 6(-2.9,-1.3) 7(-2.9,-1.95) 8(2.9,-1.95) 9(2.9,-1.3) 10(2.9,-0.65) 11(2.9,0) 12(2.9,0.65) 13(2.9,1.3) 14(2.9,1.95)
  silkscreen extent -3.53,-2.5 1.83,2.82, body extent -3.2,-2.5 3.2,2.5, height 1.25
SOP65P640X120-16N-2 [mm] "SOP,0.65mm pitch;16 pin,4.40mm W X 5.00mm L X 1.20mm H body"
  rect 1.5x0.45 smd paste+0 mask+0: 1(-2.9,2.275) 2(-2.9,1.625) 3(-2.9,0.975) 4(-2.9,0.325) 5(-2.9,-0.325) 6(-2.9,-0.975) 7(-2.9,-1.625) 8(-2.9,-2.275) 9(2.9,-2.275) 10(2.9,-1.625) 11(2.9,-0.975) 12(2.9,-0.325) 13(2.9,0.325) 14(2.9,0.975) 15(2.9,1.625) 16(2.9,2.275)
  silkscreen extent -3.02,-2.5 1.83,3.22, body extent -3.21,-2.5 3.21,2.5, height 1
SOT95P230X110-3N [mm] "SOT,0.95mm pitch;3 pin,1.30mm W X 2.90mm L X 1.10mm H body"
  rect 1x0.6 smd paste+0 mask+0: 1(-1.15,0.95) 2(-1.15,-0.95) 3(1.15,0)
  silkscreen extent -1.28,-1.45 0.33,1.87, body extent -1.15,-1.45 1.15,1.45, height 1.11
SOT95P237X112-3N-2-V [mm] "SOT,0.95mm pitch;3 pin,1.30mm W X 2.92mm L X 1.12mm H body"
  rect 0.972x0.802 smd paste+0 mask+0: 1(-0.885,0.95) 2(-0.885,-0.95) 3(0.885,0)
  silkscreen extent -2.02,-1.46 0.65,1.46, body extent -1.2,-1.46 1.2,1.46, height 1.12
SOT95P248X115-3N [mm] "SOT,0.95mm pitch;3 pin,1.315mm W X 2.95mm L X 1.15mm H body"
  rect 1.05x0.6 smd mask+0: 1(-1.15,0.95) 2(-1.15,-0.95) 3(1.15,0)
  silkscreen extent -1.52,-1.5 0.3,1.82, body extent -1.24,-1.48 1.24,1.48, height 1.16
SOT95P280X100-5N-0 [mm] "SOT,0.95mm pitch;5 pin,1.60mm W X 2.90mm L X 1.00mm H body"
  rect 1.05x0.6 smd paste+0 mask+0: 1(-1.3,0.95) 2(-1.3,0) 3(-1.3,-0.95) 4(1.3,-0.95) 5(1.3,0.95)
  silkscreen extent -1.42,-1.45 0.45,1.87, body extent -1.4,-1.45 1.4,1.45, height 1
SOT323-3AN [mm] "SOT323, 3-Leads, Body 2.0x1.3mm, Pitch 0.65mm, Lead Span 2.1mm, IPC Medium Density"
  rect 1.2x0.5 smd: 1(-0.95,0.65) 2(-0.95,-0.65) 3(0.95,0)
  silkscreen extent -1.07,-1.1 0.7,1.57, body extent -1.15,-1.05 1.15,1.05, height 1
SOT353-5N [mm] "SOT353,SC70-5, SC-88A, SOT-323-5, TSSOP-5, 5-Leads, Body 2x1.3mm, Pitch 0.65mm, Lead Span 2.1mm, IPC Medium Density"
  rect 0.85x0.4 smd: 1(-0.95,0.65) 2(-0.95,0) 3(-0.95,-0.65) 4(0.95,-0.65) 5(0.95,0.65)
  silkscreen extent -1.07,-1.1 0.15,1.52, body extent -1.15,-1.05 1.15,1.05, height 1
SOT363-6M [mm] "SOT363, 6-Leads, Body 2x1.3mm, Pitch 0.65mm, Lead Span 2.1mm, IPC Low Density"
  rect 1.05x0.4 smd: 1(-0.95,0.65) 2(-0.95,0) 3(-0.95,-0.65) 4(0.95,-0.65) 5(0.95,0) 6(0.95,0.65)
  silkscreen extent -1.07,-1.1 0.05,1.52, body extent -1.15,-1.05 1.15,1.05, height 1
TP_RD_SMD_1MM [mm] "Testpad Round 1mm Copper SMD, Hidden 3D-Body"
  round 1 smd paste-10: 1(0,0)
  body extent -0.5,-0.5 0.5,0.5, height 0.03
VSSOP50P490X110-10N [mm] "VSSOP, 10-Leads, Body 3,00x3,00mm, Pitch 0,50mm, IPC Medium Density"
  oval 1.45x0.3 smd: 1(-2.2,1) 2(-2.2,0.5) 3(-2.2,0) 4(-2.2,-0.5) 5(-2.2,-1) 6(2.2,-1) 7(2.2,-0.5) 8(2.2,0) 9(2.2,0.5) 10(2.2,1)
  silkscreen extent -2.35,-1.55 1.15,1.82, body extent -2.45,-1.55 2.45,1.55, height 1.1
XAL4030-472ME [mm] "Inductor,Chip;4.00mm L X 4.00mm W X 3.10mm H"
  rect 0.98x3.7 smd mask+0: 1(-1.185,0) 2(1.185,0)
  silkscreen extent -2.92,-2.29 2.29,2.29, body extent -2.15,-2.15 2.15,2.15, height 3.1
XFL4020 [mm] "Shilelded Power Inductors - Body 4.0mm x 4.00mm -  2 Leads"
  rect 0.98x3.4 smd: 1(-1.185,0) 2(1.185,0)
  silkscreen extent -2.3,-2.3 2.3,2.3, body extent -2.15,-2.15 2.15,2.15, height 2
XTAL-SMD-ABS07 [mm] "Crystal;3.2mm L X 1.50mm W X 0.9mm H"
  rect 1.1x1.9 smd paste+0 mask+0: 1(-1.25,0) 2(1.25,0)
  silkscreen extent -2.4,-0.75 0.3,0.75, body extent -1.6,-0.75 1.6,0.75, height 0.89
